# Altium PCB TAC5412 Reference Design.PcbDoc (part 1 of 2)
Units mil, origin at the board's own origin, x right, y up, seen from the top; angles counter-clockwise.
Board outline 3000 x 3000 mil, 6 copper layers (Top Layer, GND 1, Signal, GND 2, PWR, Bottom Layer), stack 60.4 mil thick; 137 components, 64 nets, 376 pads, 151 vias.
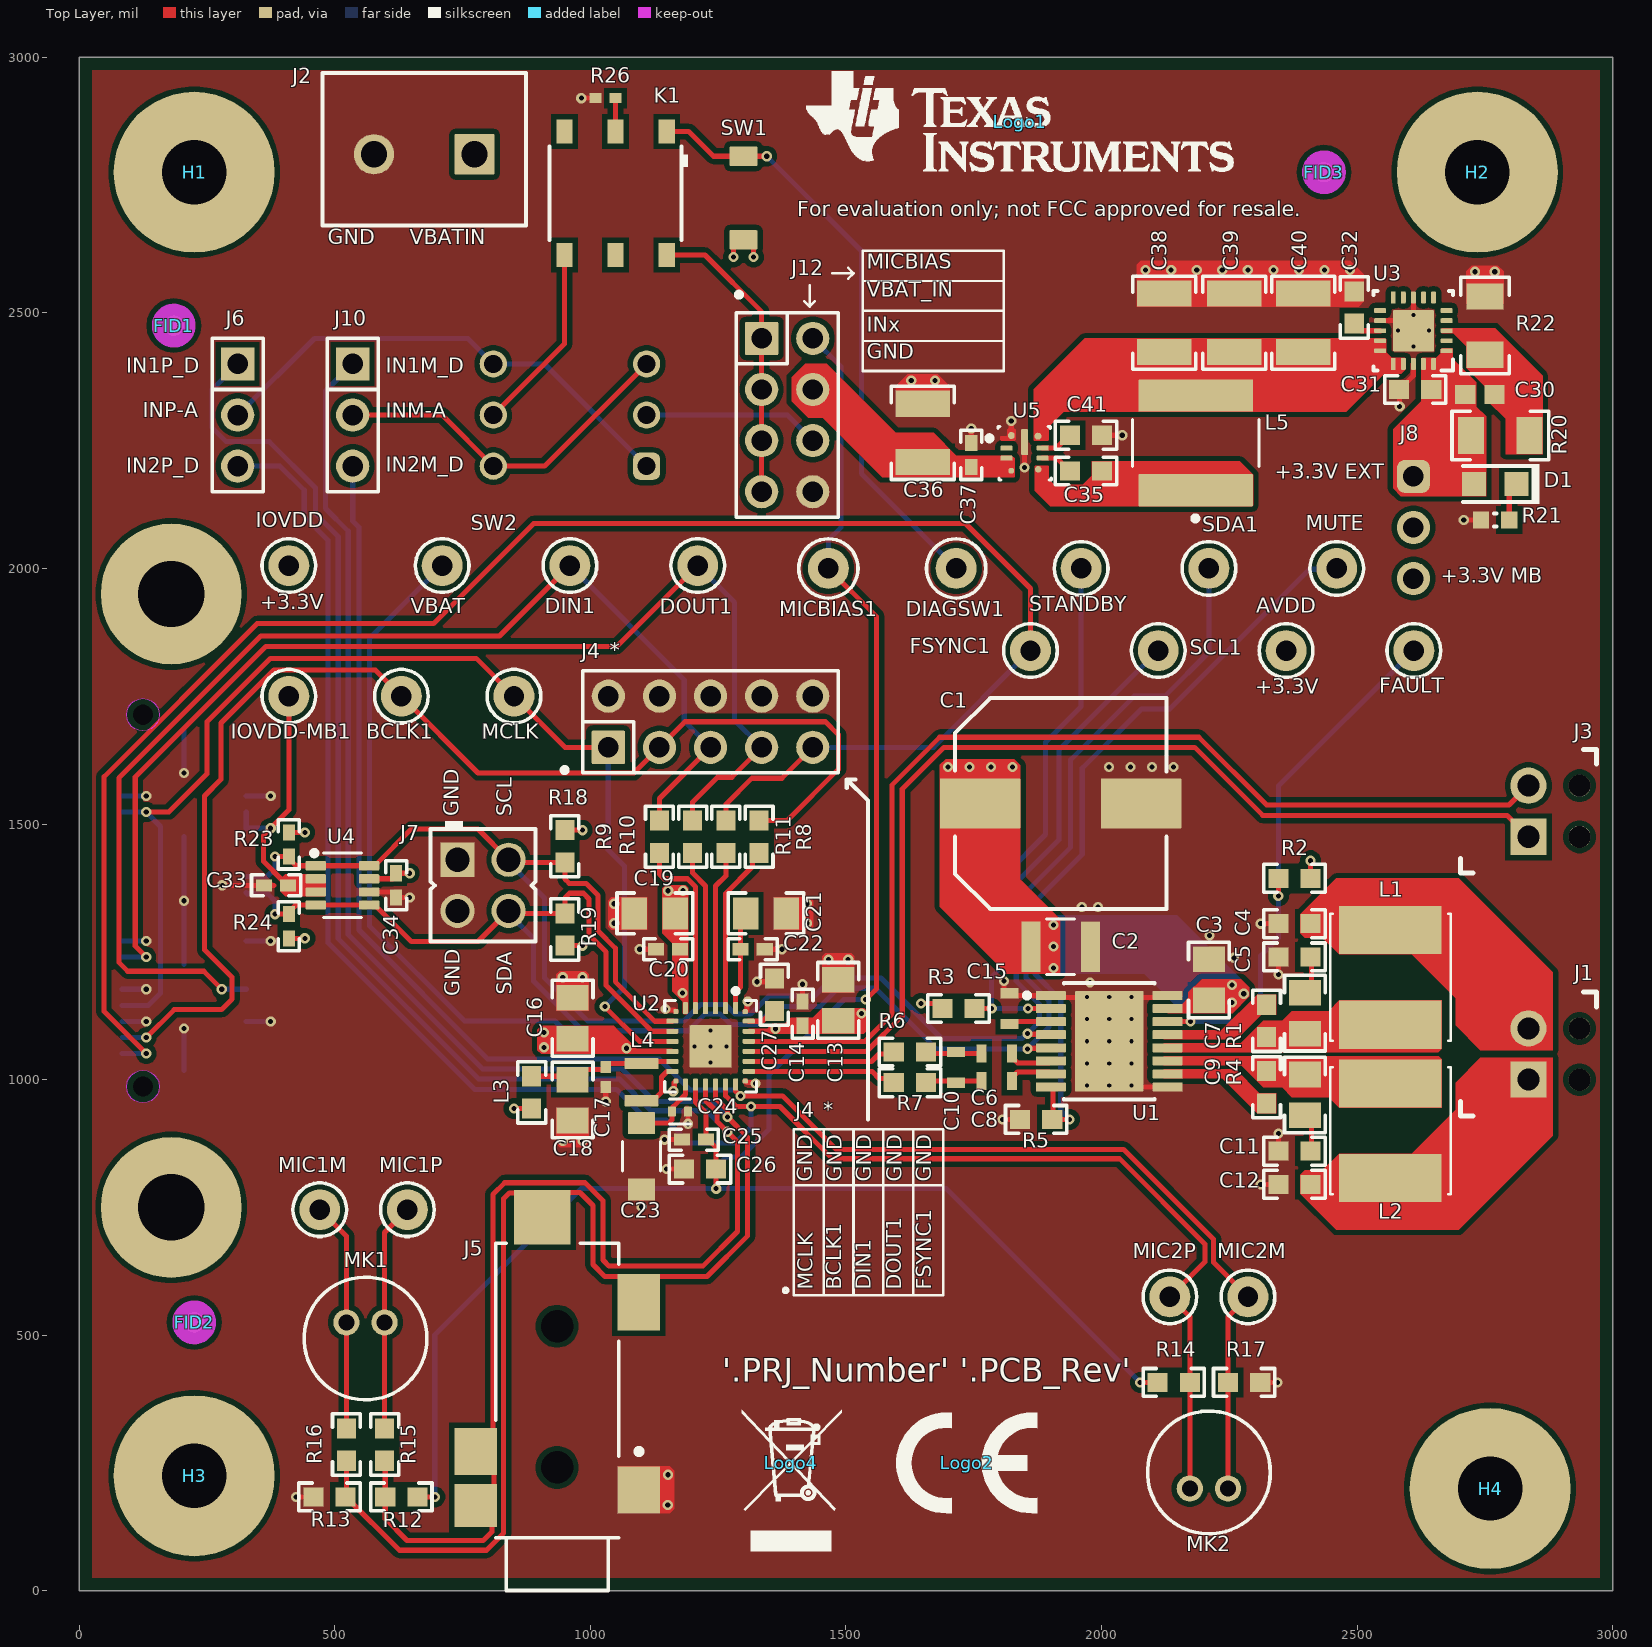
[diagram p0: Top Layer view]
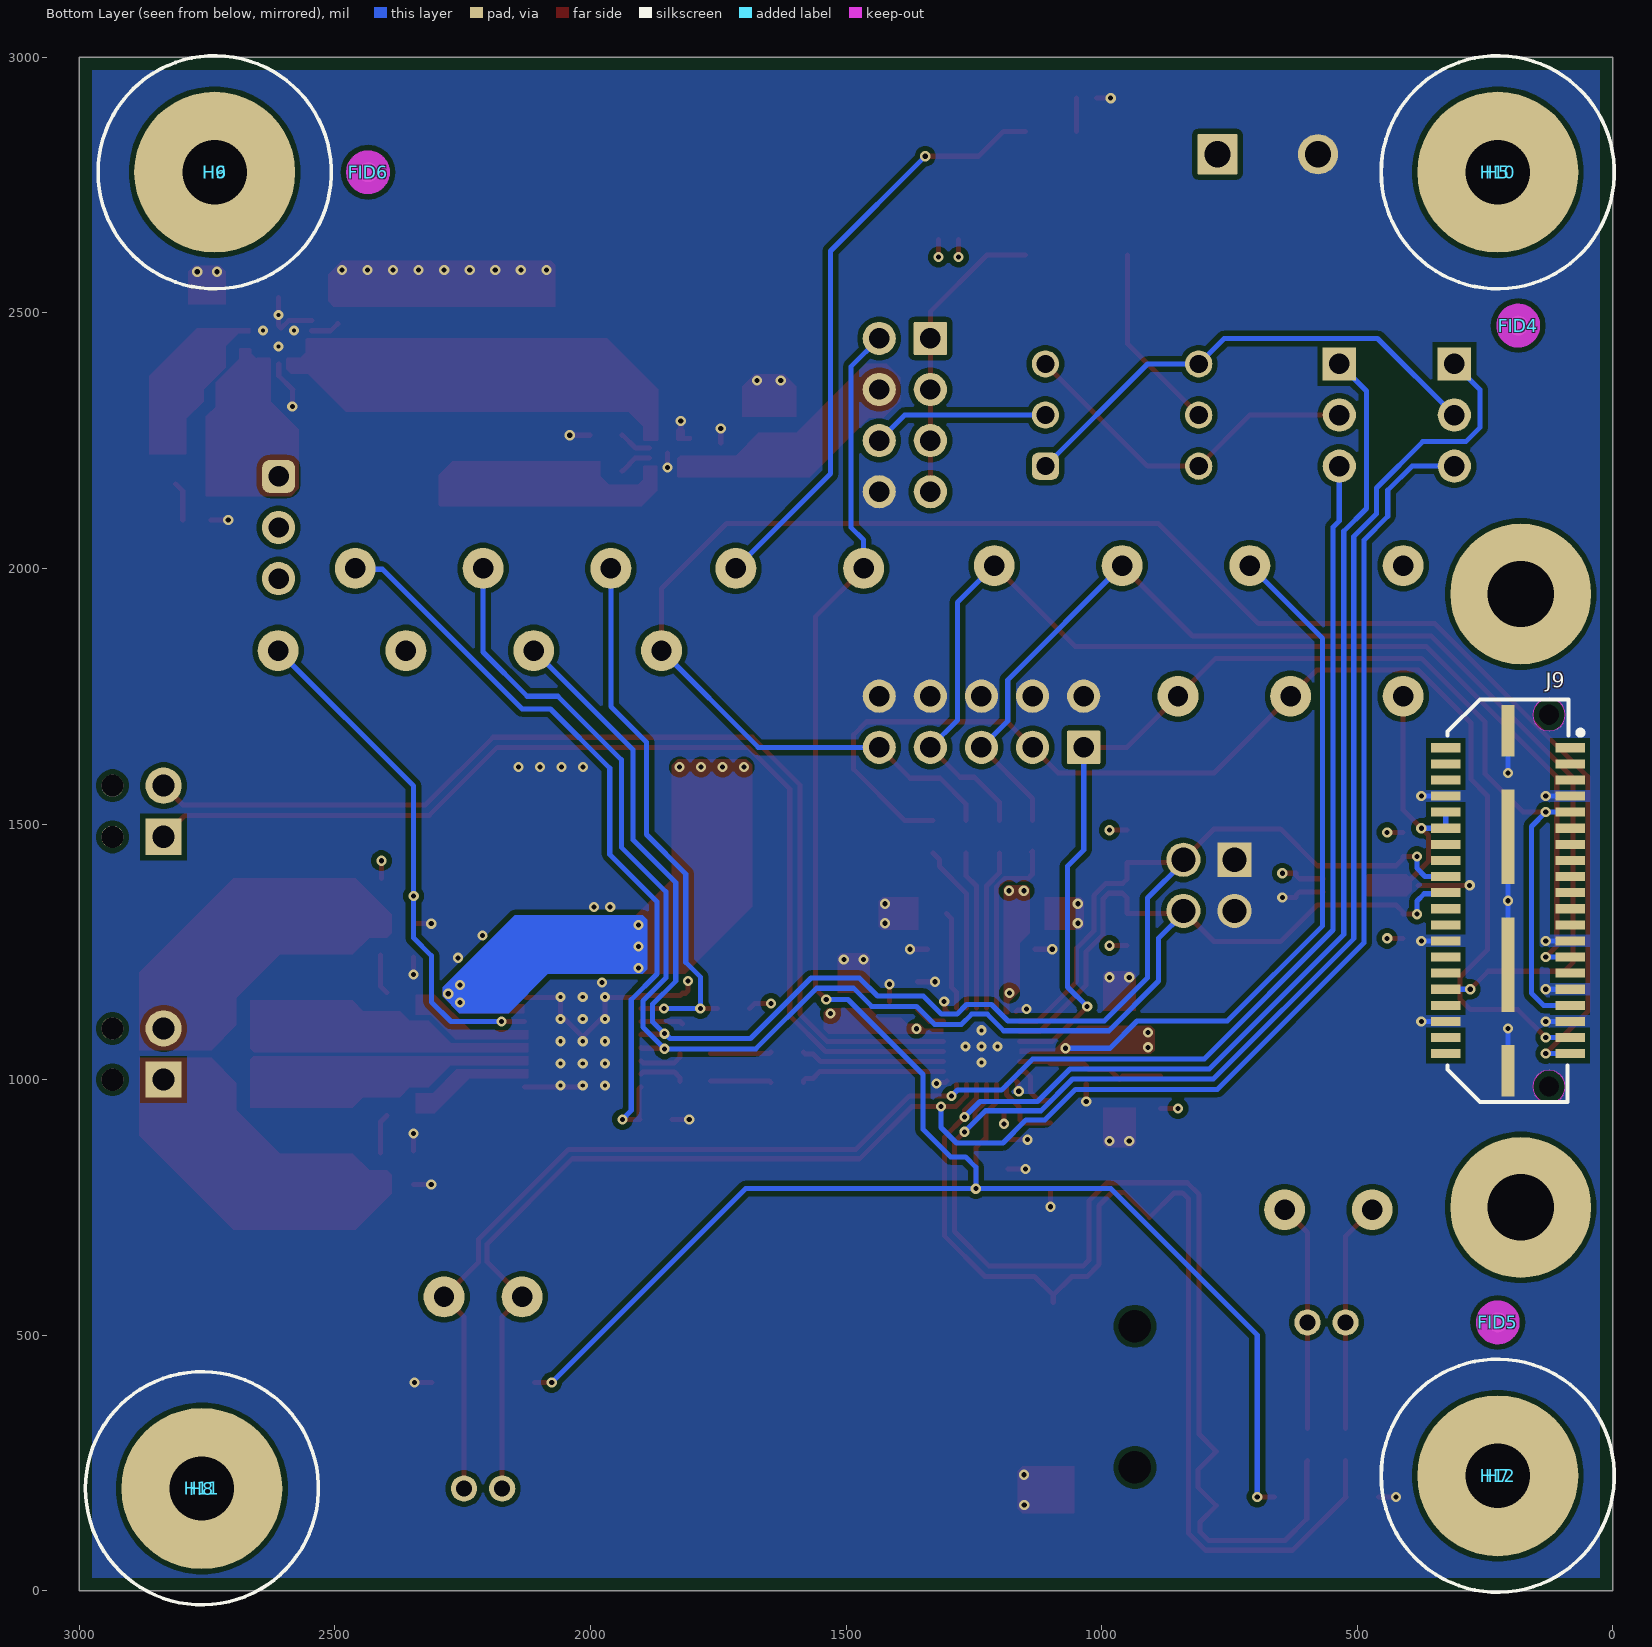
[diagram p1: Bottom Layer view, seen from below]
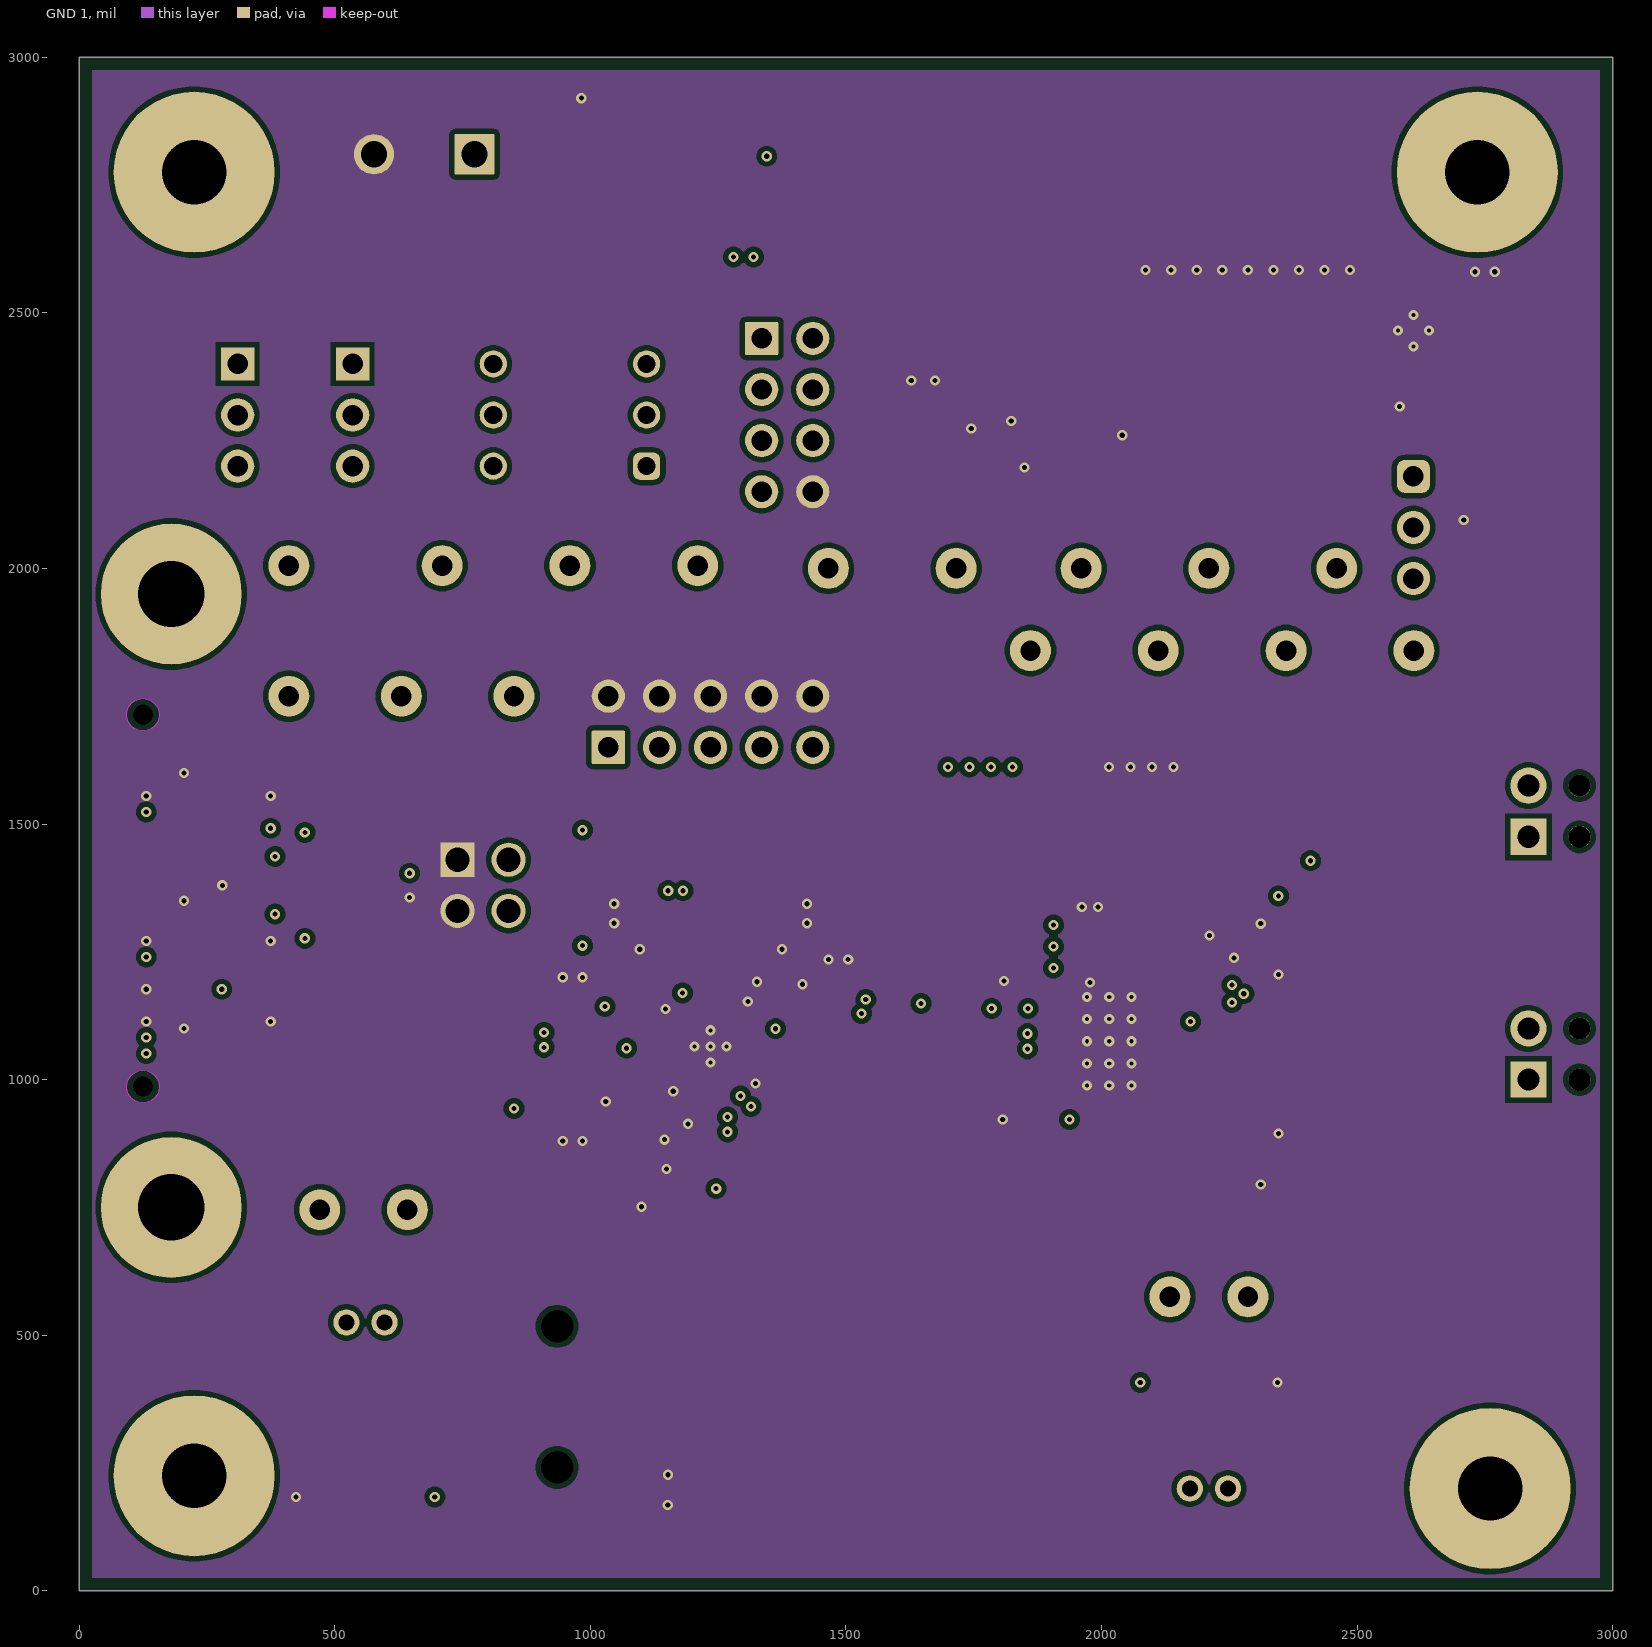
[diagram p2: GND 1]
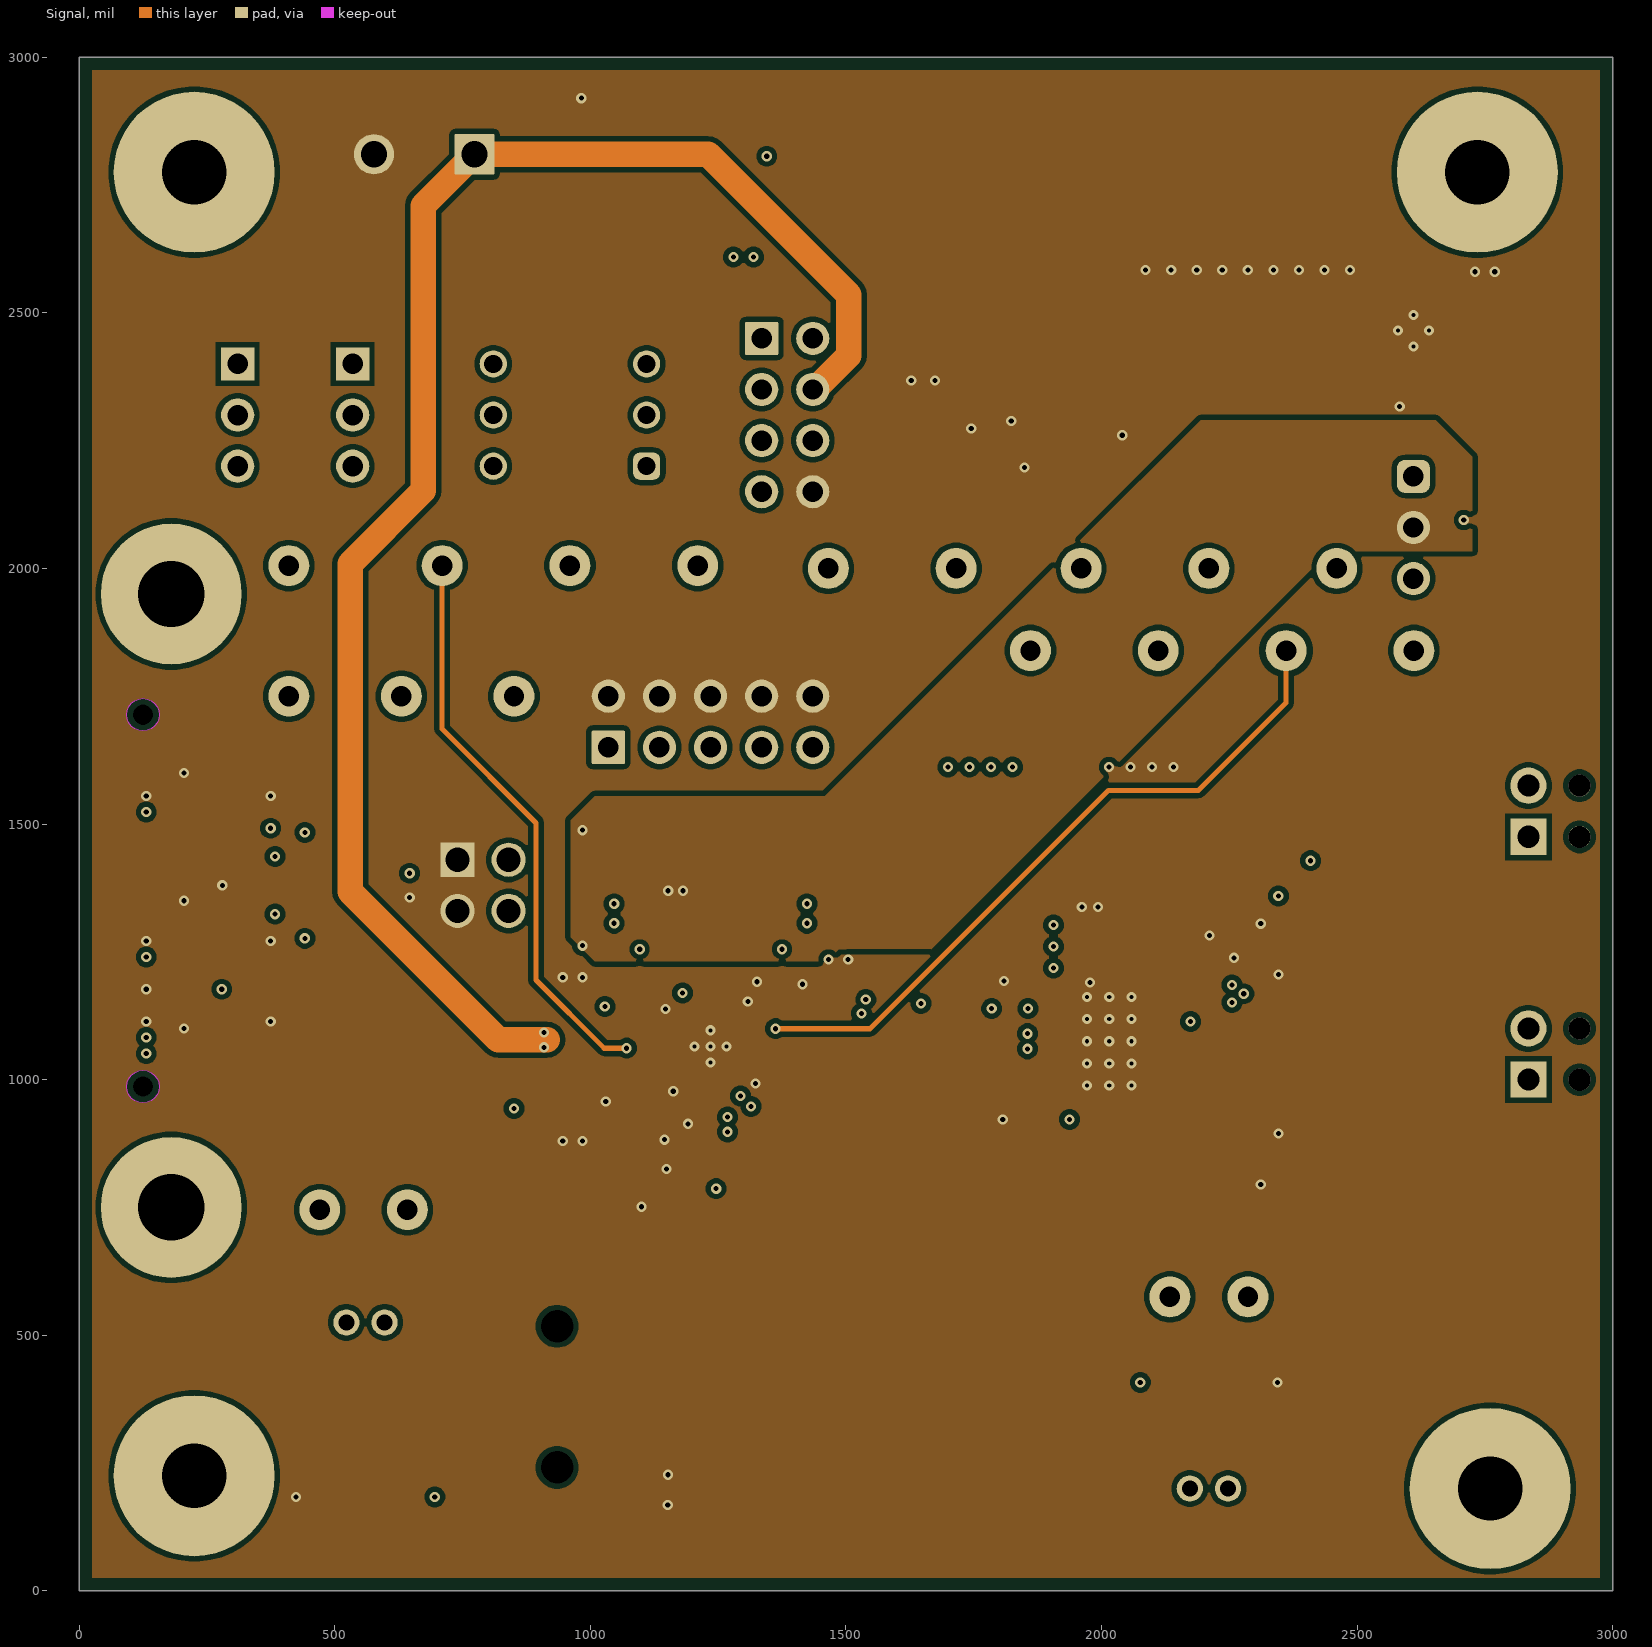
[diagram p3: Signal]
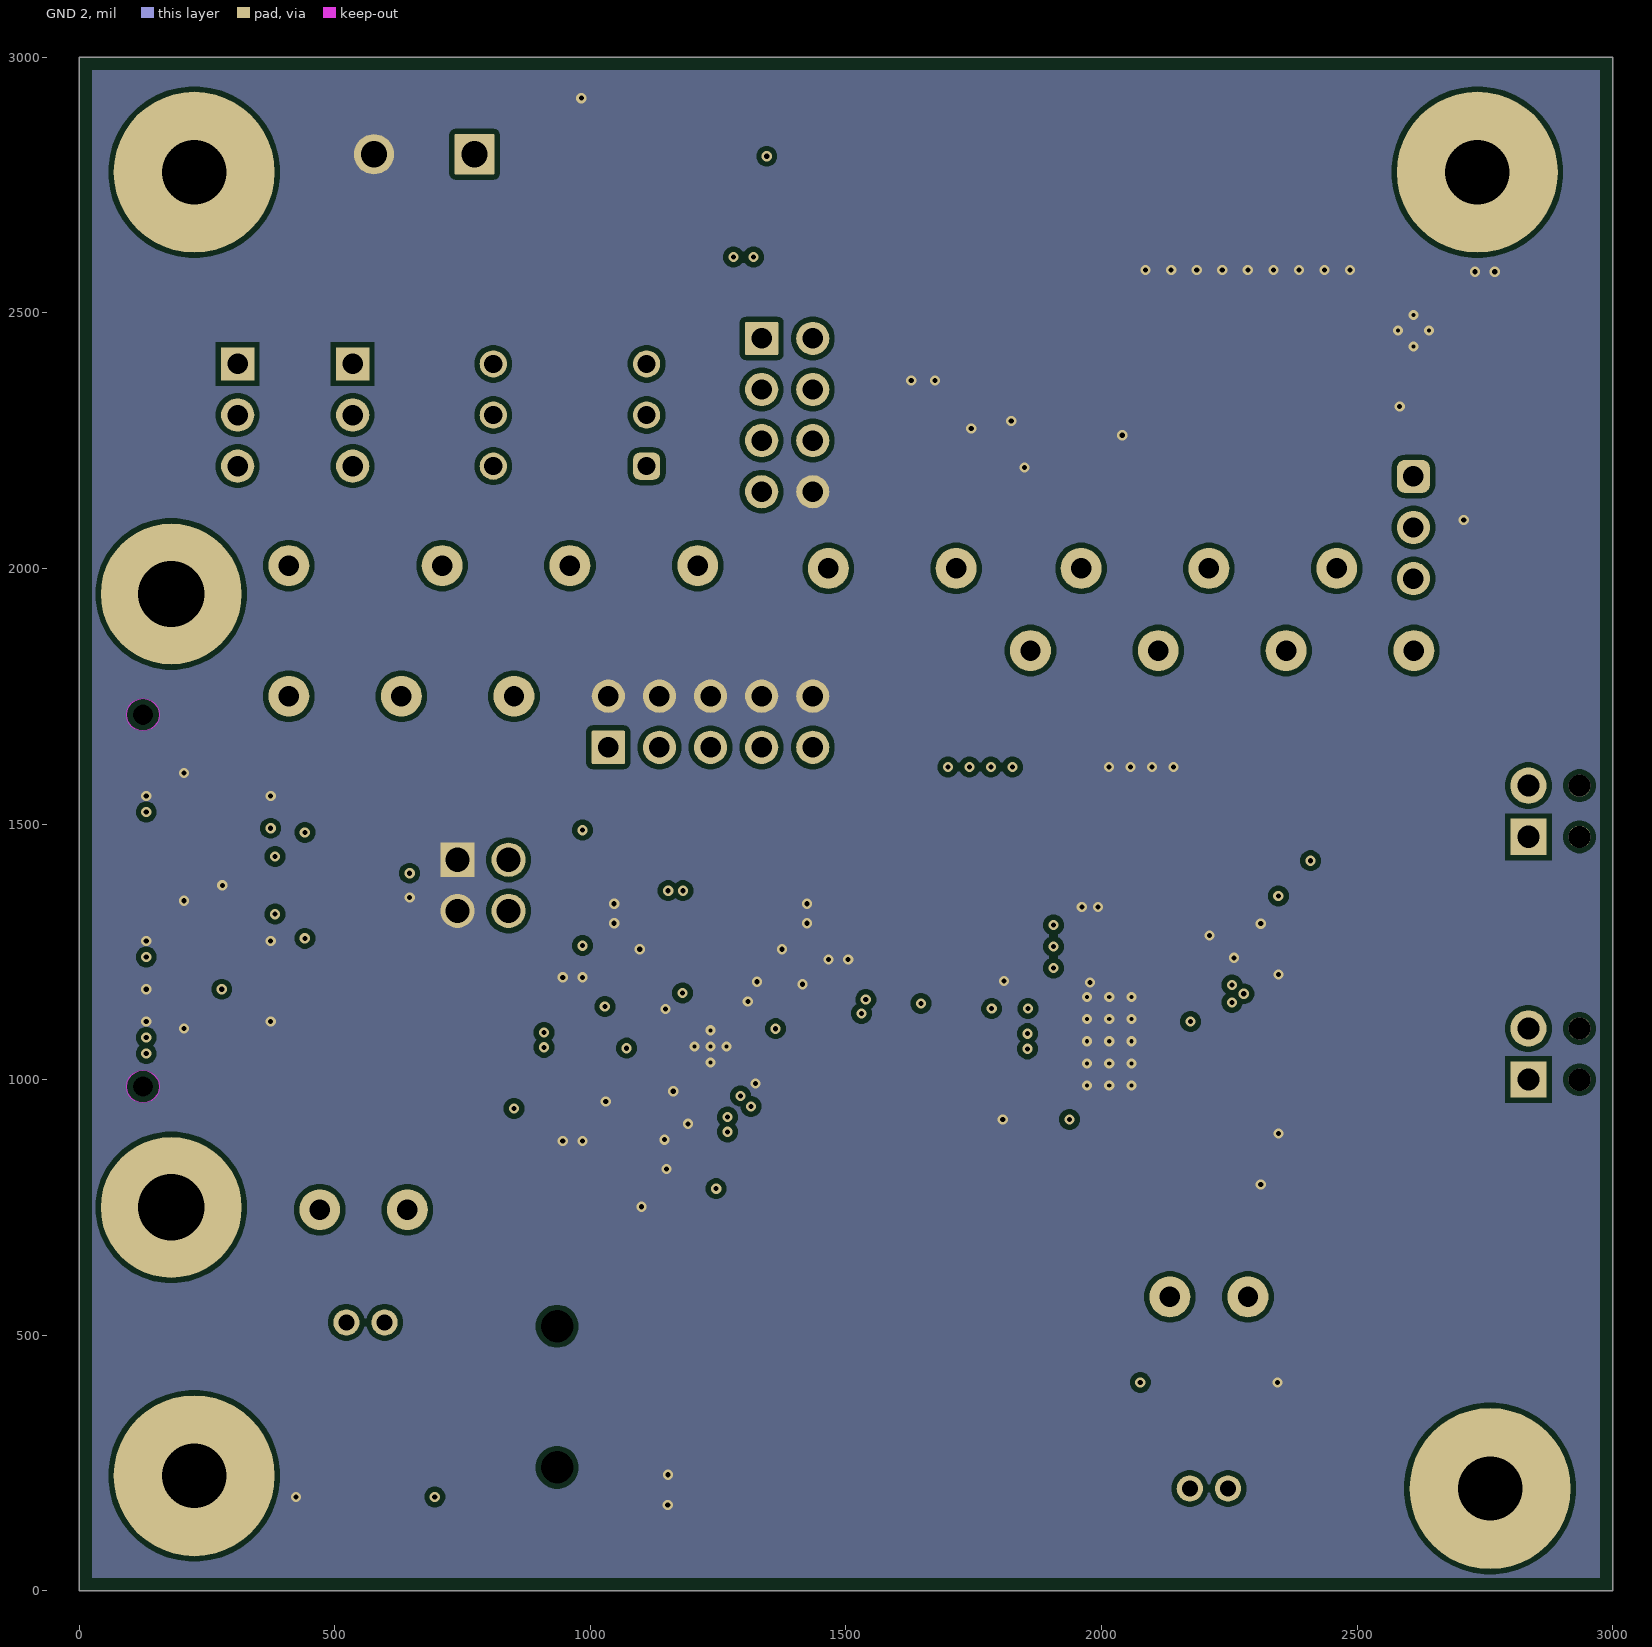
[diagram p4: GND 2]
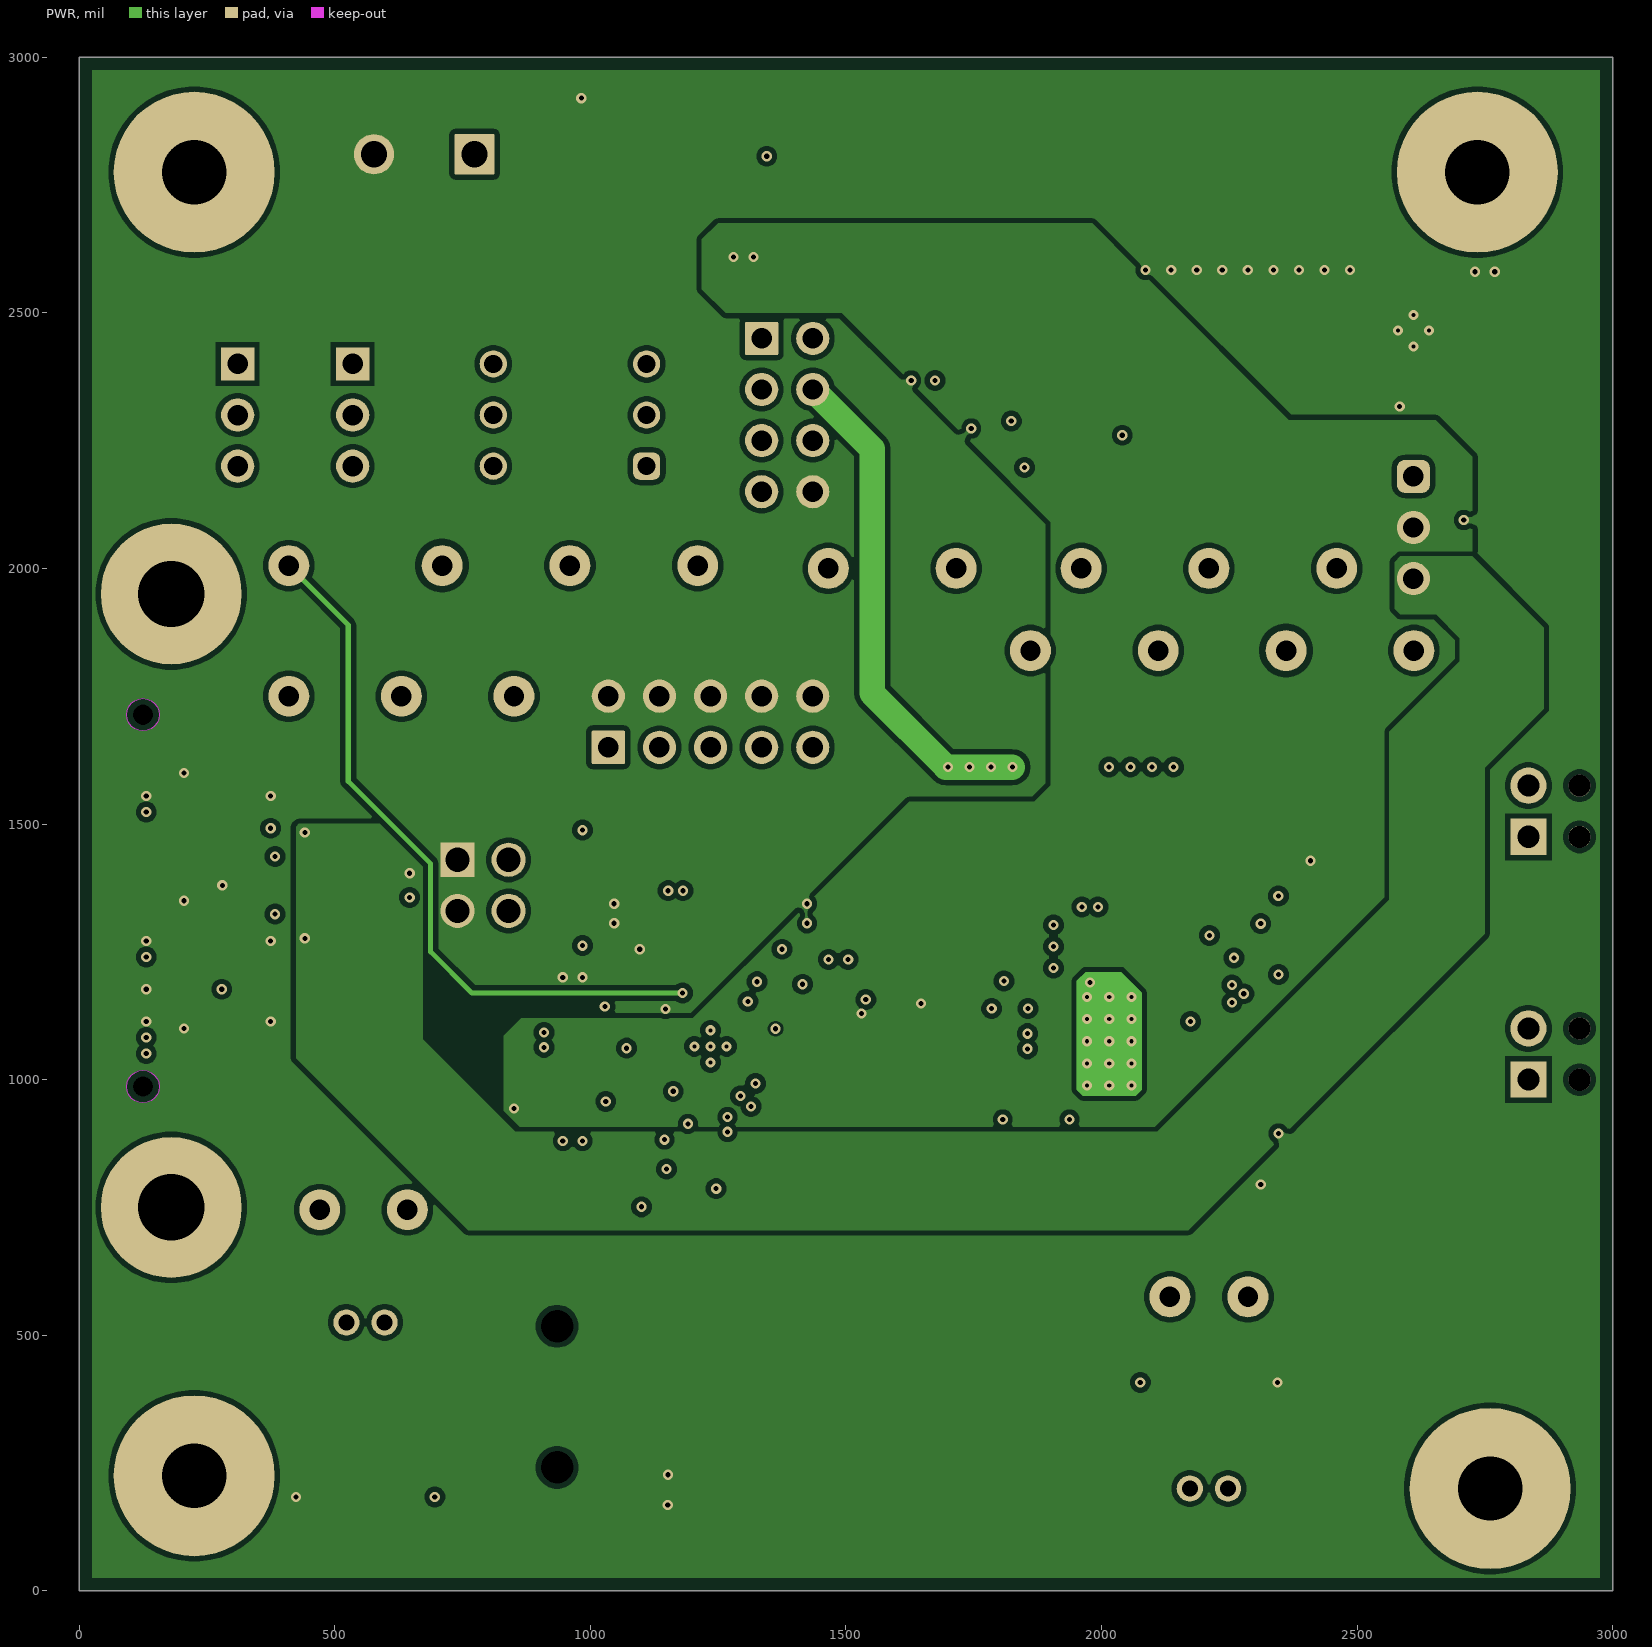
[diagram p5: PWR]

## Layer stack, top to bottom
Top Solder: solder mask 0.7, Solder Resist, Dk 3.5
Top Layer: signal copper 1.4
Dielectric 1: core 8, FR-4 High Tg, Dk 4.1
GND 1: signal copper 1.4
Dielectric 3: prepreg 8, FR-4 High Tg, Dk 4.1
Signal: signal copper 1.4
Dielectric1: core 20, FR-4 High Tg, Dk 4.1
GND 2: signal copper 1.4
Dielectric 4: prepreg 8, FR-4 High Tg, Dk 4.1
PWR: signal copper 1.4
Dielectric 2: core 8, FR-4 High Tg, Dk 4.1
Bottom Layer: signal copper 1.4
Bottom Solder: solder mask 0.7, Solder Resist, Dk 3.5

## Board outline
0,0 3000,0 3000,3000 0,3000

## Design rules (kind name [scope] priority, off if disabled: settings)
AcuteAngle [All] p1: minimum=4.50000000000000E+0001 checktracksonly=FALSE
AssemblyTestPointUsage [All] p1: valid=2
BoardOutlineClearance BoardOutlineClearance_MountingHoles [OnCopper and InComponentClass('Mounting Holes')] p1: gap=39.37 ignorepadtopadclearanceinfootprint=FALSE
BoardOutlineClearance BoardOutlineClearance_Poly [OnCopper and IsPoly] p2: gap=25 ignorepadtopadclearanceinfootprint=FALSE
BoardOutlineClearance [OnCopper and Not InComponentClass('Logo') and not InComponentClass('FiducialMark') and not InRegion(1000,500,4000,800) and not InPoly] p3: gap=40 ignorepadtopadclearanceinfootprint=FALSE
Clearance Clearance_Keepouts [((IsTrack Or IsArc) And Not InPoly) And IsFree and IsKeepOut vs ((IsTrack Or IsArc) And Not InPoly) And IsFree and IsKeepOut] p1: gap=0 ignorepadtopadclearanceinfootprint=FALSE
Clearance Clearance_Poly [InPolygon] p2: gap=10 ignorepadtopadclearanceinfootprint=TRUE
Clearance Clearance_FiducialMark [IsKeepOut and InComponentClass('FiducialMark') vs IsPad and InComponentClass('FiducialMark')] p3: gap=0 ignorepadtopadclearanceinfootprint=FALSE
Clearance [All] p4: gap=5 ignorepadtopadclearanceinfootprint=TRUE
ComponentClearance ComponentClearance_Bump [HasFootprint('Bumpon_SJ5003Transparent')] p1: gap=0 collisioncheckmode=3 verticalgap=0 showdistances=FALSE
ComponentClearance ComponentClearance_MountingHoles_FiducialMarks [InComponentClass('Mounting Holes') vs InComponentClass('FiducialMark')] p2: gap=50 collisioncheckmode=3 verticalgap=10 showdistances=FALSE
ComponentClearance ComponentClearance_Shunt [InComponentClass('Header') vs InComponentClass('Shunt')] p3: gap=0 collisioncheckmode=3 verticalgap=0 showdistances=FALSE
ComponentClearance ComponentClearance_Logo [InComponentClass('Logo')] p4: gap=30 collisioncheckmode=3 verticalgap=10 showdistances=FALSE
ComponentClearance ComponentClearance_ScrewToNut [(HasFootprint('NY PMS 440 0025 PH')) vs (HasFootprint('Keystone_1902C'))] p5: gap=5 collisioncheckmode=3 verticalgap=10 showdistances=FALSE
ComponentClearance ComponentClearance_MountingHoles [InComponentClass('Mounting Holes')] p6: gap=100 collisioncheckmode=3 verticalgap=100000 showdistances=FALSE
ComponentClearance ComponentClearance_SmallPassives [HasFootprint('0201*') or HasFootprint('0402*') or HasFootprint('0508') or HasFootprint('0603*') or HasFootprint('0612') or HasFootprint('0805*') or HasFootprint('0815*') or HasFootprint('0830*') or HasFootprint('1206*') or HasFootprint('1210*') or HasFootprint('1808*') or HasFootprint('1812*') or HasFootprint('1825*') or HasFootprint('2010*') or HasFootprint('2220*') or HasFootprint('2225*') or HasFootprint('2512*') or HasFootprint('2728*') or HasFootprint('3518*') vs HasFootprint('0201*') or HasFootprint('0402*') or HasFootprint('0508') or HasFootprint('0603*') or HasFootprint('0612') or HasFootprint('0805*') or HasFootprint('0815*') or HasFootprint('0830*') or HasFootprint('1206*') or HasFootprint('1210*') or HasFootprint('1808*') or HasFootprint('1812*') or HasFootprint('1825*') or HasFootprint('2010*') or HasFootprint('2220*') or HasFootprint('2225*') or HasFootprint('2512*') or HasFootprint('2728*') or HasFootprint('3518*')] p7: gap=14.96 collisioncheckmode=3 verticalgap=10 showdistances=FALSE
ComponentClearance ComponentClearance_THtoSMT [IsThruComponent vs IsSMTComponent] p8: gap=30 collisioncheckmode=3 verticalgap=30 showdistances=FALSE
ComponentClearance ComponentClearance_THtoTH [IsThruComponent vs IsThruComponent] p9: gap=20 collisioncheckmode=3 verticalgap=30 showdistances=FALSE
ComponentClearance [All] p10: gap=20 collisioncheckmode=3 verticalgap=10 showdistances=FALSE
DiffPairsRouting [All] p1: maxlimit=100 minlimit=10 mostfreqgap=10 toplayer_minwidth=15 toplayer_maxwidth=15 toplayer_prefwidth=15 midlayer1_minwidth=15 midlayer1_maxwidth=15 midlayer1_prefwidth=15 midlayer2_minwidth=15 midlayer2_maxwidth=15 midlayer2_prefwidth=15 midlayer3_minwidth=15 midlayer3_maxwidth=15 midlayer3_prefwidth=15 midlayer4_minwidth=15 midlayer4_maxwidth=15 midlayer4_prefwidth=15 bottomlayer_minwidth=15 bottomlayer_maxwidth=15 bottomlayer_prefwidth=15 maxuncoupledlength=1000
FabricationTestPointUsage TestPointUsage [All] p1: valid=2 allowmultiple=FALSE
FabricationTestpoint Testpoint [All] p1: side=3 testpointundercomponent=TRUE minsize=40 maxsize=100 preferedsize=60 minholesize=0 maxholesize=40 preferedholesize=32 testpointgrid=1 allowsidetop=TRUE allowsidebottom=TRUE usegrid=TRUE gridtolerance=0.01
FanoutControl Fanout_LCC [IsLCC] p1: bgadir=Out bgaviamode=Centered fanoutstyle=Auto fanoutdirection=Alternating viagrid=1 // Fanout_LCC (Default Rule)
FanoutControl Fanout_BGA [IsBGA] p2: bgadir=Out bgaviamode=Centered fanoutstyle=Auto fanoutdirection=Alternating viagrid=1 // Fanout_BGA (Default Rule)
FanoutControl Fanout_Default [All] p4: bgadir=Out bgaviamode=Centered fanoutstyle=Auto fanoutdirection=Alternating viagrid=1 // Fanout_Default (Default Rule)
FanoutControl Fanout_Small [(CompPinCount < 5)] p5: bgadir=Out bgaviamode=Centered fanoutstyle=Auto fanoutdirection=OutThenIn viagrid=1 // Fanout_Small (Default Rule)
HoleSize [All] p1: absolutevalues=TRUE maxlimit=251 minlimit=7.87 maxpercent=80.000 minpercent=20.000
MinimumAnnularRing MinimumAnnularRing_ThermalPadVias [IsVia and InAnyComponent] p1: minimumring=5.91
MinimumAnnularRing [All] p2: minimumring=5
MinimumSolderMaskSliver MinimumSolderMaskSliver_Logo [InComponentClass('Logo') vs InComponentClass('Logo')] p1: minsoldermaskwidth=0.7
MinimumSolderMaskSliver [All] p2: minsoldermaskwidth=3.94
PlaneConnect [All] p1: planeconnectstyle=Direct reliefexpansion=10 reliefentries=4 reliefconductorwidth=10 reliefairgap=10
PolygonConnect [All] p1: connectstyle=Direct reliefconductorwidth=10 reliefentries=4 polygonreliefangle="90 Angle" airgapwidth=10
RoutingVias ThermalPadVias [IsVia and InAnyComponent] p1: holewidth=7.87 width=19.68 viastyle="Through Hole" minholewidth=7.87 minwidth=19.68 maxholewidth=12.99 maxwidth=23.62
RoutingVias [All] p2: holewidth=16 width=34 viastyle="Through Hole" minholewidth=10 minwidth=20 maxholewidth=40 maxwidth=65
SilkToBoardRegionClearance [Not ((IsComment or IsDesignator) And (Hide <> 'False')) and not InRegion(1000,500,4000,800)] p1:
SilkToSilkClearance SilkToSilkClearance_Pb-FreeLogo [(HasFootprint('Pb-Free_Overlay_Medium') OR HasFootprint('Pb-Free_Overlay_Small')) vs (HasFootprint('Pb-Free_Overlay_Medium') OR HasFootprint('Pb-Free_Overlay_Small'))] p1: silktosilkclearance=0
SilkToSilkClearance [All] p2: silktosilkclearance=3.94
SilkToSolderMaskClearance SilkToComponentPadClearance [(IsPad or IsFill or IsRegion) and InAnycomponent] p1: minsilkscreentomaskgap=5 clearancetoexposedcopper=TRUE
SilkToSolderMaskClearance "Silk to Solder Mask Opening" [All] p2: minsilkscreentomaskgap=3.94 clearancetoexposedcopper=FALSE
SolderMaskExpansion [All] p1: expansion=1.97 istentingtop=FALSE
UnRoutedNet [All] p1: checkbadconnections=TRUE
Width [All] p1: maxlimit=100 minlimit=6 preferedwidth=10 checkconnectedcopper=TRUE
14 further rules are at their usual default settings.

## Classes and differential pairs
net class PWR: "+3.3V MB"
net class I2C: SCL SDA
net class ASI: BCLK1 DIN1 DIN2 DOUT1 FSYNC1
net class "16 Ohm": NetJ3_2
component class Schematic2: C30 C31 C32 C33 C34 C35 C36 C37 C38 C39 C40 C41 D1 DIAGSW1 IOVDD-MB1 J6 J8 J9 J10 J12 K1 L5 R20 R21 R22 R23 R24 R26 SW1 SW2 U3 U4 U5
component class Schematic1: AVDD BCLK1 C1 C2 C3 C4 C5 C6 C7 C8 C9 C10 C11 C12 C13 C14 C15 C16 C17 C18 C19 C20 C21 C22 C23 C24 C25 C26 C27 DIN1 DOUT1 FAULT FSYNC1 IOVDD J1 J2 J3 J4 J5 J7 L1 L2 L3 L4 MCLK MIC1M MIC1P MIC2M MIC2P MICBIAS1 MK1 MK2 MUTE R1 R2 R3 R4 R5 R6 R7 R8 R9 R10 R11 R12 R13 R14 R15 R16 R17 R18 R19 SCL1 SDA1 STANDBY U1 U2 VBAT
component class Header: J4 J6 J7 J8 J10 J12
component class "Mounting Holes": H1 H2 H3 H4
component class Logo: Logo1
component class Hardware: FID1 FID2 FID3 FID4 FID5 FID6 H1 H2 H3 H4 H5 H6 H7 H8 H9 H10 H11 H12 Logo1 Logo2 Logo3 Logo4 ZZ1 ZZ2 ZZ3 ZZ4
component class FiducialMark: FID1 FID2 FID3 FID4 FID5 FID6
component class AssemblyNote: ZZ1 ZZ2 ZZ3 ZZ4

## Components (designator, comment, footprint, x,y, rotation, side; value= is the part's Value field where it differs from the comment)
AVDD "5000" Keystone5000 2360.9,1839.35 r180 top
BCLK1 "5002" Keystone5002 630.25,1750 r180 top
C1 "UCM1H331MNL1GS" Nichicon_1000x1000 1920,1540 r0 top value=330uF
C2 "CL32B106KBJNNNE" CAP_CL32_SAM 1920,1260 r180 top
C3 "C2012X6S1H105K125AB" 0805_HV 2210,1195 r90 top value=1uF
C4 "GRM188C71E225KE11D" 0603 2377.27,1305 r180 top value=2.2uF
C5 "GRM188R72E471KW07D" 0603 2377.27,1240 r180 top value=470pF
C6 "CGA3E1X7R1E105K080AC" 0603S 1795,1051 r180 top value=1uF
C7 "GCM188R71E224KA55D" 0603 2322.75,1115 r90 top value=0.22uF
C8 "CGA3E1X7R1E105K080AC" 0603S 1795,997 r180 top value=1uF
C9 "GCM188R71E224KA55D" 0603 2322.75,985 r270 top value=0.22uF
C10 "CGA3E1X7R1E105K080AC" 0603S 1715,1024 r90 top value=1uF
C11 "GRM188R72E471KW07D" 0603 2377.27,860.02 r0 top value=470pF
C12 "GRM188C71E225KE11D" 0603 2377.27,795 r0 top value=2.2uF
C13 "EMK212BB7106KG-T" 0805_HV 1485,1155 r90 top value=10uF
C14 "885012205037" 0402 1415,1129 r90 top value=0.1uF
C15 "CGA3E1X7R1E105K080AC" 0603S 1820,1138.98 r90 top value=1uF
C16 "C2012X6S1H105K125AB" 0805_HV 965,1120 r90 top value=1uF
C17 "885012205037" 0402L 1030,1005 r270 top value=0.1uF
C18 "C2012X7R1C225K125AB" 0805_HV 965,960 r270 top value=2.2uF
C19 "EMK212BB7106KG-T" 0805_HV 1126,1325 r180 top value=10uF
C20 "885012205037" 0402 1152,1255 r180 top value=0.1uF
C21 "EMK212BB7106KG-T" 0805_HV 1343.5,1325 r0 top value=10uF
C22 "885012205037" 0402 1317.5,1255 r0 top value=0.1uF
C23 "C3216X7R1V225K160AE" FP-C3216X7R1V225K160AE_1206-MFG 1100,850 r90 top value=2.2µF
C24 "CGA2B3X7R1V104K050BB" FP-CGA2B3X7R1V104K050BB_0402-MFG 1175,937.5 r180 top value=100nF
C25 "GMK105BJ104KV-F" 0402 1202.5,882.5 r180 top value=0.1uF
C26 "C1608X7R1V105K080AC" 0603 1214.48,825 r180 top value=1uF
C27 "885012206052" 0603 1360,1166 r90 top value=1uF
C30 "C0603C103K3RACTU" CAPC17595_87N_KEM 2740,2340 r180 top
C31 "GRM188R61E106KA73D" 0603 2613.5,2350.07 r180 top value=10uF
C32 "GRM188R71E103KA01D" 0603 2494.37,2510.51 r90 top value=0.01uF
C33 "885012205037" 0402 385,1380 r0 top value=0.1uF
C34 "885012205037" 0402 620,1380 r90 top value=0.1uF
C35 "GCM188R71C105KA64J" 0603 1969.37,2190.51 r0 top value=1uF
C36 "GCM32ER71H475KA55L" 1210_270 1650,2265.09 r90 top value=4.7uF
C37 "GCM155R71H104KE02D" 0402 1745,2221.89 r90 top value=0.1uF
C38 "GRM32ER61E226KE15L" 1210_270 2122.28,2480.51 r90 top value=22uF
C39 "GRM32ER61E226KE15L" 1210_270 2259.37,2480.51 r90 top value=22uF
C40 "GRM32ER61E226KE15L" 1210_270 2394.37,2480.51 r90 top value=22uF
C41 "GCM188R71C105KA64J" 0603 1969.37,2260.51 r0 top value=1uF
D1 "LTST-C170KGKT" LTST-C170KGKT_Green 2770,2165 r0 top value=Green
DIAGSW1 "SHORT A" Keystone_5116 1715.5,2000 r90 top
DIN1 "5002" Keystone5002 960,2005.5 r0 top
DOUT1 "5002" Keystone5002 1210,2005.5 r0 top
FAULT "5002" Keystone5002 2610.9,1839.35 r180 top
FID1 "Fiducial" Fiducial10-20 185,2475 r0 top
FID2 "Fiducial" Fiducial10-20 225,525 r0 top
FID3 "Fiducial" Fiducial10-20 2435,2775 r0 top
FID4 "Fiducial" Fiducial10-20 185,2475 r180 bottom
FID5 "Fiducial" Fiducial10-20 225,525 r180 bottom
FID6 "Fiducial" Fiducial10-20 2435,2775 r180 bottom
FSYNC1 "5002" Keystone5002 1860.9,1839.35 r180 top
H1 "NY PMS 440 0025 PH" "NY PMS 440 0025 PH" 225,2775 r0 top
H2 "NY PMS 440 0025 PH" "NY PMS 440 0025 PH" 2735,2775 r0 top
H3 "NY PMS 440 0025 PH" "NY PMS 440 0025 PH" 225,225 r0 top
H4 "NY PMS 440 0025 PH" "NY PMS 440 0025 PH" 2760,200 r0 top
H5 "1902C" Keystone_1902C 225,2775 r0 bottom
H6 "1902C" Keystone_1902C 2735,2775 r0 bottom
H7 "1902C" Keystone_1902C 225,225 r0 bottom locked
H8 "1902C" Keystone_1902C 2760,200 r0 bottom
H9 "SJ-5303 (CLEAR)" Bumpon_SJ5003Transparent 2735,2775 r270 bottom
H10 "SJ-5303 (CLEAR)" Bumpon_SJ5003Transparent 225,2775 r270 bottom
H11 "SJ-5303 (CLEAR)" Bumpon_SJ5003Transparent 2760,200.5 r270 bottom
H12 "SJ-5303 (CLEAR)" Bumpon_SJ5003Transparent 225,225 r270 bottom
IOVDD "5000" Keystone5000 410,2005.5 r0 top
IOVDD-MB1 "5000" Keystone5000 410,1750 r180 top
J1 "1725656" CONN_1725656 2835,1050 r90 top
J2 "691137710002" FP-691137710002_HDR2-MFG 675,2820 r180 top
J3 "1725656" CONN_1725656 2835,1525 r90 top
J4 "TSW-105-07-G-D" TSW-105-07-G-D 1235,1700 r0 top
J5 "35RASMT4BHNTRX" Switchcraft_35RASM 935,340 r180 top
J6 "PBC03SAAN" PBC03SAAN 310,2300 r270 top
J7 "I2C" Sullins_PxC02DAAN 790,1380 r0 top
J8 "TSW-103-07-G-S" TSW-103-07-G-S 2610,2080 r270 top
J9 "QTE-020-01-L-D-A" QTE-020-01-X-D-A 205,1350 r270 bottom
J10 "PBC03SAAN" PBC03SAAN 535,2300 r270 top
J12 "TSW-104-07-G-D" TSW-104-07-G-D 1385,2300 r270 top
K1 "G3VM-31HR(TR05)" Omron_SOP-6 1049.36,2733.92 r270 top
L1 "VLS6045EX-100M-H" IND_VLS6045EX-100M-H 2565,1200 r90 top
L2 "VLS6045EX-100M-H" IND_VLS6045EX-100M-H 2565,900 r270 top
L3 "782633601" 0603 885,975 r270 top value="600 ohm"
L4 "LPWI201610H2R2T" 0806 1100,995 r270 top value=2.2uH
L5 "1255AY-3R9N=P3" "FP-1255AY-3R9N=P3_2424 (6060)-MFG" 2184.37,2245.51 r90 top value=3.9uH
Logo1 "Texas Instruments" TI_Stacked_Overlay_Small 1840.29,2874.23 r0 top
Logo2 "CE Mark" CE_Mark_5mm 1736.1,250 r0 top
Logo3 "FCC disclaimer" FCC_disclaimer 3681.67,-180 r0 top
Logo4 "WEEE logo" WEEE_Minimum 1391.96,250 r0 top
MCLK "5002" Keystone5002 850.5,1750 r180 top
MIC1M "5003" Keystone5003 470.61,745.48 r0 top
MIC1P "5003" Keystone5003 641.99,745.48 r0 top
MIC2M "5003" Keystone5003 2286.38,575 r0 top
MIC2P "5003" Keystone5003 2133.62,575 r0 top
MICBIAS1 "MBIAS" Keystone_5116 1465.5,2000 r90 top
MK1 "POM-2242P-C33-R" MIC_POM-2242P-C33-R 560,525 r180 top
MK2 "POM-2242P-C33-R" MIC_POM-2242P-C33-R 2210,200 r0 top
MUTE "5002" Keystone5002 2460,2000 r0 top
R1 "RL1220S-5R6-F" 0805_HV 2397.75,1130 r270 top value=5.60
R2 "CPF0603B100KE" 0603 2377.27,1393.68 r180 top value=100k
R3 "CPF0603B100KE" 0603 1720,1138.98 r0 top value=100k
R4 "RL1220S-5R6-F" 0805_HV 2397.75,970 r270 top value=5.60
R5 "CPF0603B100KE" 0603 1872.01,922 r0 top value=100k
R6 "RC0603JR-070RL" 0603 1625,1054 r0 top value=0
R7 "RC0603JR-070RL" 0603 1625,994 r0 top value=0
R8 "PMR03EZPJ000" 0603 1330,1475 r90 top value=0
R9 "PMR03EZPJ000" 0603 1135,1475 r90 top value=0
R10 "PMR03EZPJ000" 0603 1200,1475 r90 top value=0
R11 "PMR03EZPJ000" 0603 1265,1475 r90 top value=0
R12 "CRCW06031K10JNEA" 0603 630.18,183.55 r0 top value=1.1k
R13 "CRCW06031K10JNEA" 0603 489.59,183.62 r180 top value=1.1k
R14 "CRCW06031K10JNEA" 0603 2141.1,407.5 r0 top value=1.1k
R15 "RC0603JR-070RL" 0603 597.4,285.94 r270 top value=0
R16 "RC0603JR-070RL" 0603 522.6,285.94 r270 top value=0
R17 "CRCW06031K10JNEA" 0603 2278.9,407.5 r0 top value=1.1k
R18 "RC0603FR-071K5L" 0603 950,1456.5 r270 top value=1.50k
R19 "RC0603FR-071K5L" 0603 950,1293.5 r90 top value=1.50k
R20 "CRCW120611K8FKEA" 1206 2780,2260 r180 top value=11.8k
R21 "CRCW0603442RFKEA" 0603L 2770,2095 r180 top value=442
R22 "CRCW12063K74FKEA" 1206 2750,2475 r270 top value=3.74k
R23 "RMCF0402FT1K50" 0402 410,1460 r90 top value=1.50k
R24 "RMCF0402FT1K50" 0402 410,1300 r270 top value=1.50k
R26 "CRCW0402330RJNED" 0402L 1029.68,2919.9 r0 top value=330
SCL1 "5002" Keystone5002 2110.9,1839.35 r180 top
SDA1 "5002" Keystone5002 2210,2000 r0 top
STANDBY "5002" Keystone5002 1960,2000 r0 top
SW1 "TEST A" SW_TL1015AF160QG 1299.36,2724.58 r90 top
SW2 "76STD01T" SW_76STD01T 960,2300 r180 top
U1 "TAS5441QPWPRQ1" PWP0016B-MFG 2015,1075 r0 top
U2 "TAC5312QRGERQ1" RGE0024W-MFG 1235,1065 r270 top
U3 "TPS7A5201QRGRRQ1" RGR0020A 2610,2465 r180 top
U4 "TCA9416DDFR" SOT_16DDFR_TEX 515,1380 r0 top
U5 "LMR43620RS5QRPERQ1" RPE0009A-MFG 1849.37,2225.51 r0 top
VBAT "5000" Keystone5000 710,2005.5 r0 top
ZZ1 "This Assembly Note is for PCB labels only" AssemblyNoteLabel 41.26,3399.26 r0 top
ZZ2 "These assemblies are ESD sensitive, ESD precautions shall be observed." AssemblyNote 41.26,3290.37 r0 top
ZZ3 "These assemblies must be clean and free from flux and all contaminants. Use of no clean flux is not acceptable." AssemblyNote 41.26,3201.82 r0 top
ZZ4 "These assemblies must comply with workmanship standards IPC-A-610 Class 2, unless otherwise specified." AssemblyNote 41.26,3113.26 r0 top

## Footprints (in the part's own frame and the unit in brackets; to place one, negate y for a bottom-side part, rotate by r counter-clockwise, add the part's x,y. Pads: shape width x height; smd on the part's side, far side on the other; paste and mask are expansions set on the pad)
0402 [mm] "0402 from SM-752 data"
  rect 0.8x0.6 smd: 1(-0.6,0) 2(0.6,0)
  silkscreen extent -1.22,-0.52 1.22,0.52, body extent -0.55,-0.3 0.55,0.3, height 0.6
0402L [mm] "0402 from SM-752 data"
  rect 0.6x0.5 smd: 1(-0.5,0) 2(0.5,0)
  body extent -0.55,-0.3 0.55,0.3, height 0.6
0603 [mm] "0603 from SM-752 data"
  rect 1x0.95 smd: 1(-0.8,0) 2(0.8,0)
  silkscreen extent -1.52,-0.69 1.52,0.69, body extent -0.87,-0.47 0.87,0.47, height 1
0603L [mm] "0603 from SM-752 data"
  rect 0.8x0.85 smd: 1(-0.7,0) 2(0.7,0)
  silkscreen extent -0.07,-0.32 0.07,0.32, body extent -0.87,-0.47 0.87,0.47, height 1
0603S [mil]
  rect 20x35 smd: 1(-30,0) 2(30,0)
  body extent -34,-19 34,19, height 39
0805_HV [mil] "0805 with 30mil clearance between pads"
  rect 50x63 smd: 1(-40,0) 2(40,0)
  silkscreen extent -74,-40 74,40, body extent -43,-29 43,29, height 57
0806 [mm] "SMD, 2-Leads, Body 2x1.6mm"
  rrect18% 0.55x1.7 smd: 1(-0.925,0) 2(0.925,0)
  body extent -1.2,-0.85 1.2,0.85, height 1
1206 [mm] "1206 from SM-752 data"
  rect 1.3x1.85 smd: 1(-1.45,0) 2(1.45,0)
  silkscreen extent -2.4,-1.21 2.4,1.21, body extent -1.7,-0.9 1.7,0.9, height 1.35
1210_270 [mm] "1210"
  rect 1.3x2.7 smd: 1(-1.45,0) 2(1.45,0)
  silkscreen extent -2.32,-1.57 2.32,1.57, body extent -1.7,-1.35 1.7,1.35, height 2.7
AssemblyNote [mil] "Assembly Note"
AssemblyNoteLabel [mil] "Assembly Note for PCB Labels"
Bumpon_SJ5003Transparent [mil] "3M Hemispherical Bumpon transparent"
  round 1 on Mech4: 0(0,0)
  silkscreen extent -228,-228 228,228, body extent -219,-219 219,219, height 197
CAP_CL32_SAM [mm] "1210 from SM-752 data"
  rect 0.956x2.5 smd paste+0 mask+0: 1(-1.478,0) 2(1.478,0)
  silkscreen extent -0.69,-1.38 0.69,1.38, body extent -1.6,-1.25 1.6,1.25, height 1
CAPC17595_87N_KEM [mm]
  rect 1.006x0.95 smd paste+0 mask+0: 1(-0.728,0) 2(0.728,0)
  body extent -0.87,-0.48 0.87,0.48, height 0.87
CE_Mark_5mm [mil] "Minimum text height for CE Mark"
  silkscreen extent -138,-98 138,98
CONN_1725656 [mm] "Phoenix Contact"
  rect 1.8x1.8 hole 1.1: 1(-1.27,0)
  round 1.8 hole 1.1: 2(1.27,0)
  round 1.1 hole 1.1 unplated: MH1(-1.275,-2.54) MH2(1.27,-2.54)
  silkscreen extent -3.08,-3.37 3.08,3.37, body extent -2.77,-3.1 2.77,3.1, height 8.52
FCC_disclaimer [mil]
Fiducial10-20 [mm]
  round 1 smd mask+0.5: 1(0,0)
  Top Layer keep-out circle w1.178: c0,0 r0.5
"FP-1255AY-3R9N=P3_2424 (6060)-MFG" [mm]
  rrect6% 1.6x5.7 smd paste+0 mask+0: 1(-2.35,0) 2(2.35,0)
  silkscreen extent -3.87,-3.15 1.17,3.15, body extent -3.25,-3.25 3.25,3.25, height 0.25
FP-691137710002_HDR2-MFG [mm]
  rrect5% 2x2 hole 1.3 paste-1000 mask+0: 1(-2.5,0.25)
  round 2 hole 1.3 paste-1000 mask+0: 2(2.5,0.25)
  silkscreen extent -5.05,-3.8 5.05,3.8, body extent -5.15,-3.9 5.15,3.9, height 0.25
FP-C3216X7R1V225K160AE_1206-MFG [mm]
  rrect9% 1.1x1.35 smd paste+0 mask+0: 1(-1.65,0) 2(1.65,0)
  silkscreen extent -0.72,-0.95 0.73,0.95, body extent -2.3,-1.05 2.3,1.05, height 0.25
FP-CGA2B3X7R1V104K050BB_0402-MFG [mm]
  rrect25% 0.4x0.5 smd paste+0 mask+0: 1(-0.4,0) 2(0.4,0)
  silkscreen extent -0.52,-0.63 0.53,0.63, body extent -0.7,-0.38 0.7,0.38, height 0.25
IND_VLS6045EX-100M-H [mm]
  rect 2.4x5.1 smd: 1(-2.35,0) 2(2.35,0)
  silkscreen extent -3.15,-3 3.15,3, body extent -3.15,-3 3.15,3, height 4.5
Keystone5000 [mil] "For Keystone 500x miniature loop terminals"
  round 80 hole 40: 1(0,0)
  silkscreen extent -52,-52 52,52, body extent -49,-49 49,49, height 182
Keystone5002 [mil] "For Keystone 500x miniature loop terminals"
  round 80 hole 40: 1(0,0)
  silkscreen extent -52,-52 52,52, body extent -49,-49 49,49, height 182
Keystone5003 [mil] "For Keystone 500x miniature loop terminals"
  round 80 hole 40: 1(0,0)
  silkscreen extent -52,-52 52,52, body extent -49,-49 49,49, height 182
Keystone_1902C [mil] "Hex Standoff, 4-40 threaded, nylon"
  round 1 on Mech4: 0(0,0)
  body extent -145,-126 146,126, height 501
Keystone_5116 [mil] "For Keystone 500x miniature loop terminals"
  round 80 hole 40: 1(0,0)
  silkscreen extent -58,-58 58,58, body extent -50,-49 50,51, height 183
LTST-C170KGKT_Green [mm] "LITE-ON"
  rect 1.2x1.2 smd: 1(-1.05,0) 2(1.05,0)
  silkscreen extent -1.6,-1 2.2,1, body extent -1.05,-0.67 1.05,0.67, height 1.1
MIC_POM-2242P-C33-R [mm] "POM Audio"
  round 1.3 hole 0.8: 1(-0.95,0) 2(0.95,0)
  silkscreen extent -3.05,-2.25 3.05,3.85, body extent -3.05,-2.24 3.05,3.84, height 2.5
Nichicon_1000x1000 [mm] "SMD, 2-Leads, Dia 10mm"
  rrect4% 4x2.5 smd: 1(-4,0) 2(4,0)
  silkscreen extent -5.25,-5.25 5.25,5.25, body extent -5.25,-5.25 5.25,5.25, height 10.81
"NY PMS 440 0025 PH" [mm] "4-40 nylon screw and mounting hole"
  round 8 hole 3.2: 1(0,0)
  body extent -3.3,-3.3 3.3,3.3, height 2.69
Omron_SOP-6 [mm] "SOP, 6-Leads, Body 6.3x4.4mm, Pitch 2.54mm"
  rect 1.2x0.8 smd: 1(-3.075,2.54) 2(-3.075,0) 3(-3.075,-2.54) 4(3.075,-2.54) 5(3.075,0) 6(3.075,2.54)
  silkscreen extent -2.32,-3.28 2.32,3.6, body extent -2.32,-3.28 2.32,3.27, height 2.11
PBC03SAAN [mm] "Sullins 100mil, 1x3, 230 mil above insulator"
  rect 1.65x1.65 hole 1.016: 1(-2.54,0)
  round 1.65 hole 1.016: 2(0,0) 3(2.54,0)
  silkscreen extent -3.81,-1.27 3.81,1.27, body extent -3.81,-1.27 3.81,1.27, height 8.38
PWP0016B-MFG [mm]
  rrect22% 1.5x0.45 smd paste+0 mask+0: 1(-2.9,2.275) 2(-2.9,1.625) 3(-2.9,0.975) 4(-2.9,0.325) 5(-2.9,-0.325) 6(-2.9,-0.975) 7(-2.9,-1.625) 8(-2.9,-2.275) 9(2.9,-2.275) 10(2.9,-1.625) 11(2.9,-0.975) 12(2.9,-0.325) 13(2.9,0.325) 14(2.9,0.975) 15(2.9,1.625) 16(2.9,2.275)
  rrect3% 3.4x5 smd paste-1000 mask-1000: 17(0,0)
  silkscreen extent -4.22,-2.9 2.25,2.9, body extent -3.75,-2.8 3.75,2.8, height 0.25
QTE-020-01-X-D-A [mm] "0.80mm pitch, 40 pin, high speed terminal strip"
  rect 0.45x1.45 smd: 1(-7.6,3.09) 2(-7.6,-3.09) 3(-6.8,3.09) 4(-6.8,-3.09) 5(-6,3.09) 6(-6,-3.09) 7(-5.2,3.09) 8(-5.2,-3.09) 9(-4.4,3.09) 10(-4.4,-3.09) 11(-3.6,3.09) 12(-3.6,-3.09) 13(-2.8,3.09) 14(-2.8,-3.09) 15(-2,3.09) 16(-2,-3.09) 17(-1.2,3.09) 18(-1.2,-3.09) 19(-0.4,3.09) 20(-0.4,-3.09) 21(0.4,3.09) 22(0.4,-3.09) 23(1.2,3.09) 24(1.2,-3.09) 25(2,3.09) 26(2,-3.09) 27(2.8,3.09) 28(2.8,-3.09) 29(3.6,3.09) 30(3.6,-3.09) 31(4.4,3.09) 32(4.4,-3.09) 33(5.2,3.09) 34(5.2,-3.09) 35(6,3.09) 36(6,-3.09) 37(6.8,3.09) 38(6.8,-3.09) 39(7.6,3.09) 40(7.6,-3.09)
  rect 2.55x0.65 smd: 41(-8.445,0) 44(8.445,0)
  rect 4.7x0.65 smd: 42(-3.175,0) 43(3.175,0)
  round 0.5 hole 1 unplated: 45(-9.24,2.04) 46(9.24,2.04)
  Keep-Out Layer pour cut-out: 10.047,2.04 10.019,2.249 9.939,2.443 9.811,2.611 9.643,2.739 9.449,2.819 9.24,2.847 9.031,2.819 8.837,2.739 8.669,2.611 8.541,2.443 8.461,2.249 8.433,2.04 8.461,1.831 8.541,1.637 8.669,1.469 8.837,1.341 9.031,1.261 9.24,1.233 9.449,1.261 9.643,1.341 9.811,1.469 9.939,1.637 10.019,1.831
  Keep-Out Layer pour cut-out: -8.433,2.04 -8.461,2.249 -8.541,2.443 -8.669,2.611 -8.837,2.739 -9.031,2.819 -9.24,2.847 -9.449,2.819 -9.643,2.739 -9.811,2.611 -9.939,2.443 -10.019,2.249 -10.047,2.04 -10.019,1.831 -9.939,1.637 -9.811,1.469 -9.643,1.341 -9.449,1.261 -9.24,1.233 -9.031,1.261 -8.837,1.341 -8.669,1.469 -8.541,1.637 -8.461,1.831
  silkscreen extent -10,-3 10,3.72, body extent -10.01,-3.56 9.99,3.56, height 4.27
RGE0024W-MFG [mm]
  rrect40% 0.6x0.25 smd paste+0 mask+0: 1(-1.9,1.25) 2(-1.9,0.75) 3(-1.9,0.25) 4(-1.9,-0.25) 5(-1.9,-0.75) 6(-1.9,-1.25) 13(1.9,-1.25) 14(1.9,-0.75) 15(1.9,-0.25) 16(1.9,0.25) 17(1.9,0.75) 18(1.9,1.25)
  rrect40% 0.25x0.6 smd paste+0 mask+0: 7(-1.25,-1.9) 8(-0.75,-1.9) 9(-0.25,-1.9) 10(0.25,-1.9) 11(0.75,-1.9) 12(1.25,-1.9) 19(1.25,1.9) 20(0.75,1.9) 21(0.25,1.9) 22(-0.25,1.9) 23(-0.75,1.9) 24(-1.25,1.9)
  rrect5% 2.1x2.1 smd paste-1000 mask+0: 25(0,0)
  rrect40% 0.25x0.25 smd paste+0 mask+0: A1(-1.725,1.725) A2(-1.725,-1.725) A3(1.725,-1.725) A4(1.725,1.725)
  silkscreen extent -2.87,-2.27 2.27,2.27, body extent -2.3,-2.3 2.3,2.3, height 0.25
RGR0020A [mm] "QFN, 20-Leads, Body 3.5x3.5mm, Pitch 0.5mm, Thermal Pad 2.05x2.05mm, TI Recommended"
  rrect42% 0.6x0.24 smd: 1(-1.65,1) 2(-1.65,0.5) 3(-1.65,0) 4(-1.65,-0.5) 5(-1.65,-1) 11(1.65,-1) 12(1.65,-0.5) 13(1.65,0) 14(1.65,0.5) 15(1.65,1)
  rrect42% 0.24x0.6 smd: 6(-1,-1.65) 7(-0.5,-1.65) 8(0,-1.65) 9(0.5,-1.65) 10(1,-1.65) 16(1,1.65) 17(0.5,1.65) 18(0,1.65) 19(-0.5,1.65) 20(-1,1.65)
  rrect5% 2.05x2.05 smd paste-1.025: 21(0,0)
  silkscreen extent -1.97,-1.97 1.97,1.97, body extent -1.75,-1.75 1.75,1.75, height 1
RPE0009A-MFG [mm]
  round 0.342 smd paste-1000 mask+0: 1(-0.661,0.877)
  rrect40% 0.6x0.25 smd paste+0 mask+0: 2(-0.9,0.25) 3(-0.9,-0.25) 6(0.9,-0.25) 7(0.9,0.25)
  round 0.291 smd paste+0 mask+0: 4(-0.661,-0.877)
  round 0.323 smd paste+0 mask+0: 5(0.68,-0.805)
  round 0.346 smd paste-1000 mask+0: 8(0.665,0.841)
  rrect29% 0.35x1.3 smd paste-1000 mask+0: 9(0,0.55)
  Top Layer region: 1.2,0.8 1.193,0.825 1.175,0.844 1.15,0.85 1.15,0.85 0.9,0.851 0.881,0.854 0.865,0.865 0.854,0.881 0.85,0.901 0.85,0.901 0.85,1.15 0.843,1.175 0.825,1.193 0.8,1.2 0.8,1.2 0.5,1.2 0.481,1.196 0.465,1.185 0.454,1.169 0.45,1.15 0.45,1.15 0.45,0.676 0.454,0.656 0.465,0.64 0.481,0.629 0.5,0.625 0.5,0.625 1.15,0.626 1.169,0.629 1.185,0.64 1.196,0.656 1.2,0.675 1.2,0.676
  Top Layer region: -1.2,0.8 -1.193,0.826 -1.175,0.844 -1.15,0.851 -1.15,0.851 -0.9,0.851 -0.881,0.854 -0.865,0.865 -0.854,0.881 -0.85,0.901 -0.85,0.901 -0.85,1.15 -0.843,1.175 -0.825,1.193 -0.8,1.2 -0.8,1.2 -0.5,1.2 -0.481,1.196 -0.465,1.185 -0.454,1.169 -0.45,1.15 -0.45,1.15 -0.45,0.676 -0.454,0.656 -0.465,0.64 -0.481,0.629 -0.5,0.626 -0.5,0.625 -1.15,0.626 -1.169,0.629 -1.185,0.64 -1.196,0.656 -1.2,0.676 -1.2,0.676
  Top Layer region: 1.2,-0.8 1.193,-0.825 1.175,-0.844 1.15,-0.85 1.15,-0.851 0.9,-0.85 0.881,-0.854 0.865,-0.865 0.854,-0.881 0.85,-0.9 0.85,-0.901 0.85,-1.15 0.843,-1.175 0.825,-1.193 0.8,-1.2 0.8,-1.2 0.55,-1.2 0.531,-1.196 0.515,-1.185 0.504,-1.169 0.5,-1.15 0.5,-1.15 0.5,-0.676 0.504,-0.656 0.515,-0.64 0.531,-0.629 0.55,-0.625 0.55,-0.625 1.15,-0.626 1.169,-0.629 1.185,-0.64 1.196,-0.656 1.2,-0.676 1.2,-0.676
  Top Layer region: -1.2,-0.8 -1.193,-0.825 -1.175,-0.844 -1.15,-0.85 -1.15,-0.85 -0.9,-0.851 -0.881,-0.854 -0.865,-0.865 -0.854,-0.881 -0.85,-0.901 -0.85,-0.901 -0.85,-1.15 -0.843,-1.175 -0.825,-1.193 -0.8,-1.2 -0.8,-1.2 -0.55,-1.2 -0.531,-1.196 -0.515,-1.185 -0.504,-1.169 -0.5,-1.15 -0.5,-1.15 -0.5,-0.676 -0.504,-0.656 -0.515,-0.64 -0.531,-0.629 -0.55,-0.625 -0.55,-0.625 -1.15,-0.626 -1.169,-0.629 -1.185,-0.64 -1.196,-0.656 -1.2,-0.676 -1.2,-0.676
  silkscreen extent -1.87,-1.33 1.33,1.33, body extent -1.3,-1.3 1.3,1.3, height 0.25
SOT_16DDFR_TEX [mil]
  rrect20% 39.5x18 smd paste+0 mask+0: 1(-52.25,38.39) 2(-52.25,12.8) 3(-52.25,-12.8) 4(-52.25,-38.39) 5(52.25,-38.39) 6(52.25,-12.8) 7(52.25,12.8) 8(52.25,38.39)
  silkscreen extent -60,-63 38,68, body extent -58,-58 58,58, height 43
Sullins_PxC02DAAN [mm] "Header, 2.54mm, 2x2, TH"
  rect 1.7x1.7 hole 1.2: 1(-1.27,1.27)
  round 1.7 hole 1.2: 2(1.27,1.27) 3(-1.27,-1.27) 4(1.27,-1.27)
  silkscreen extent -2.61,-2.8 2.61,3.2, body extent -2.61,-2.8 2.61,2.8, height 8.58
SW_76STD01T [mm] "TH, 6-Leads, Body 9.65x9.65mm"
  rrect50% 1.35x1.35 hole 0.9: 1(-3.81,2.54)
  round 1.35 hole 0.9: 2(-3.81,0) 3(-3.81,-2.54) 4(3.81,-2.54) 5(3.81,0) 6(3.81,2.54)
  body extent -4.83,-4.83 4.82,4.83, height 11.86
SW_TL1015AF160QG [mm] "E-Switch"
  rrect11% 0.95x1.4 smd: 1(-2.075,0) 2(2.075,0)
  body extent -2.3,-1.5 2.3,1.5, height 2
Switchcraft_35RASM [mil] "Switchcraft"
  rect 83x92 smd: 1(-159.5,142.5) 2(159.5,67.5)
  rect 83x111 smd: 3(-159.5,-224.5)
  rect 83x84 smd: 4(159.5,173.5)
  rect 111x107 smd: 5(29,-390.5)
  rect 0x0 hole 63 unplated: MH1(0,98.5) MH2(0,-177.5)
  silkscreen extent -161,-340 121,340, body extent -120,-339 120,340, height 202
TI_Stacked_Overlay_Small [mil]
  silkscreen extent -418,-98 418,98
TSW-103-07-G-S [mm] "Samtec 100mil, 1x3, 230 mil above insulator"
  rrect50% 1.65x1.65 hole 1.016: 1(-2.54,0)
  round 1.65 hole 1.016: 2(0,0) 3(2.54,0)
  body extent -3.81,-1.27 3.81,1.27, height 8.38
TSW-104-07-G-D [mm] "Samtec 100mil, 2x4, 230 mil above insulator"
  rrect6% 1.65x1.65 hole 1.016: 1(-3.81,-1.27)
  round 1.65 hole 1.016: 2(-3.81,1.27) 3(-1.27,-1.27) 4(-1.27,1.27) 5(1.27,-1.27) 6(1.27,1.27) 7(3.81,-1.27) 8(3.81,1.27)
  silkscreen extent -6.1,-2.54 5.08,2.54, body extent -5.08,-2.54 5.08,2.54, height 8.38
TSW-105-07-G-D [mm] "Samtec 100mil, 2x5, 230 mil above insulator"
  rrect6% 1.65x1.65 hole 1.016: 1(-5.08,-1.27)
  round 1.65 hole 1.016: 2(-5.08,1.27) 3(-2.54,-1.27) 4(-2.54,1.27) 5(0,-1.27) 6(0,1.27) 7(2.54,-1.27) 8(2.54,1.27) 9(5.08,-1.27) 10(5.08,1.27)
  silkscreen extent -7.37,-2.54 6.35,2.54, body extent -6.35,-2.54 6.35,2.54, height 8.38
WEEE_Minimum [mil] "WEEElie bin"
  silkscreen extent -95,-172 99,104

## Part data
AVDD IOVDD IOVDD-MB1 VBAT: library part CMP-0055137-2, "Test Point, Miniature, Red, TH", Color=Red, Manufacturer="Keystone Electronics", Supplier Part Number 1=36-5000-ND
BCLK1 DIN1 DOUT1 FAULT FSYNC1 MCLK MUTE SCL1 SDA1 STANDBY: library part CMP-0055139-2, "Test Point, Miniature, White, TH", Color=White, Manufacturer="Keystone Electronics", Supplier Part Number 1=36-5002-ND
C1: library part CMP-0064900-1, "CAP, AL, 330 uF, 50 V, +/- 20%, SMD", Cap_Case=10x10mm, Manufacturer=Nichicon, Supplier Part Number 1=493-14535-1-ND, Tolerance_%=20%, Value1=Unknown, Value2=50V, ValueDisplayed=330uF
C2: "No Description Available", Mfr_Name=Samsung
C3 C16: library part CMP-0007855-1, "CAP, CERM, 1 uF, 50 V, +/- 10%, X6S, 0805", Cap_Case=0805, Manufacturer=TDK, Supplier Part Number 1=445-7595-1-ND, TempCo=X6S, Tolerance_%=10%, Value1="0.008782 ohm", Value2=50V, ValueDisplayed=1uF
C4 C12: library part CMP-0075366-3, "CAP, CERM, 2.2 µF, 25 V,+/- 10%, X7S, 0603", Cap_Case=0603, Manufacturer=MuRata, Supplier Part Number 1=490-12732-1-ND, TempCo=X7S, Tolerance_%=10%, Value2=25V, ValueDisplayed=2.2µF
C5 C11: library part CMP-0007495-4, "CAP, CERM, 470 pF, 250 V, +/- 10%, X7R, 0603", Cap_Case=0603, Manufacturer=MuRata, Supplier Part Number 1=490-3523-1-ND, TempCo=X7R, Tolerance_%=10%, Value1=Unknown, Value2=250V, ValueDisplayed=470pF
C6 C8 C10 C15: library part CMP-0076705-3, "CAP, CERM, 1 µF, 25 V,+/- 10%, X7R, AEC-Q200 Grade 1, 0603", Cap_Case=1.6x0.8x0.8mm, Manufacturer=TDK, Supplier Part Number 1=445-6931-1-ND, TempCo=X7R, Tolerance_%=10%, Value2=25V, ValueDisplayed=1µF
C7 C9: library part CMP-0007140-4, "CAP, CERM, 0.22 uF, 25 V, +/- 10%, X7R, AEC-Q200 Grade 1, 0603", Cap_Case=0603, Manufacturer=MuRata, Supplier Part Number 1=490-4935-1-ND, TempCo=X7R, Tolerance_%=10%, Value1=Unknown, Value2=25V, ValueDisplayed=0.22uF
C13 C19 C21: library part CMP-0085283-1, "CAP, CERM, 10 µF, 16 V,+/- 10%, X7R, 0805", Cap_Case=0805, Manufacturer="Taiyo Yuden", TempCo=X7R, Tolerance_%=10%, Value2=16V, ValueDisplayed=10µF
C14 C17 C20 C22 C33 C34: library part CMP-0006228-2, "CAP, CERM, 0.1 uF, 16 V, +/- 10%, X7R, 0402", Cap_Case=0402, Manufacturer="Wurth Elektronik", Supplier Part Number 1=732-7532-1-ND, TempCo=X7R, Tolerance_%=10%, Value1=Unknown, Value2=16V, ValueDisplayed=0.1uF
C18: library part CMP-0007867-2, "CAP, CERM, 2.2 uF, 16 V, +/- 10%, X7R, 0805", Cap_Case=0805, Manufacturer=TDK, Supplier Part Number 1=445-1420-1-ND, TempCo=X7R, Tolerance_%=10%, Value1="0.0049 ohm", Value2=16V, ValueDisplayed=2.2uF
C23: library part CMP-0096782-1, "Capacitor Ceramic 2.2uF 35V X7R 10% 1206 T/R", Digikey Part Number=445-173825-1-ND, Manufacturer=TDK, Mouser Part Number=810-C3216X7R1V225KAE, Operating Temperature Range="-55°C to +125°C", TempCo=15%, Temperature Characteristic=X7R, Tolerance_%=10%, ValueDisplayed=2.2uF
C24: library part CMP-0094936-1, "Cap Ceramic 100nF 35V X7R 10% Pad SMD 0402 +125°C Automotive T/R", Manufacturer="TDK Corporation", Operating Temperature Range="-55°C to +125°C", TempCo=15%, Temperature Characteristic=X7R, Tolerance_%=0.1%, ValueDisplayed=100nF
C25: library part CMP-0006370-2, "CAP, CERM, 0.1 uF, 35 V, +/- 10%, X5R, 0402", Cap_Case=0402, Manufacturer="Taiyo Yuden", Supplier Part Number 1=587-1994-1-ND, TempCo=X5R, Tolerance_%=10%, Value1=Unknown, Value2=35V, ValueDisplayed=0.1uF
C26: library part CMP-0007052-4, "CAP, CERM, 1 uF, 35 V, +/- 10%, X7R, 0603", Cap_Case=0603, Manufacturer=TDK, Supplier Part Number 1=445-7414-1-ND, TempCo=X7R, Tolerance_%=10%, Value1=Unknown, Value2=35V, ValueDisplayed=1uF
C27: library part CMP-0006831-4, "CAP, CERM, 1 uF, 16 V, +/- 10%, X7R, 0603", Cap_Case=0603, Manufacturer="Wurth Elektronik", Supplier Part Number 1=710-885012206052, TempCo=X7R, Tolerance_%=10%, Value1=Unknown, Value2=16V, ValueDisplayed=1uF
C30: "No Description Available", Mfr_Name=Kemet
C31: library part CMP-0860569-1, "CAP, CERM, 10 µF, 25 V,+/- 10%, X5R, 0603", Cap_Case=0603, Manufacturer=MuRata, TempCo=X5R, Tolerance_%=10%, Value2=25V, ValueDisplayed=10µF
C32: library part CMP-0007403-4, "CAP, CERM, 0.01 uF, 25 V, +/- 10%, X7R, 0603", Cap_Case=0603, Manufacturer=MuRata, Supplier Part Number 1=490-1520-1-ND, TempCo=X7R, Tolerance_%=10%, Value1=Unknown, Value2=25V, ValueDisplayed=0.01uF
C35 C41: library part CMP-0079154-1, "CAP, CERM, 1 µF, 16 V,+/- 10%, X7R, AEC-Q200 Grade 1, 0603", Cap_Case=0603, Manufacturer=MuRata, Supplier Part Number 1=490-12657-1-ND, TempCo=X7R, Tolerance_%=10%, Value2=16V, ValueDisplayed=1µF
C36: library part CMP-0750153-1, "CAP, CERM, 4.7 µF, 50 V,+/- 10%, X7R, AEC-Q200 Grade 1, 1210", Cap_Case=1210, Manufacturer=MuRata, TempCo=X7R, Tolerance_%=10%, Value2=50V, ValueDisplayed=4.7µF
C37: library part CMP-0006356-2, "CAP, CERM, 0.1 uF, 50 V, +/- 10%, X7R, AEC-Q200 Grade 1, 0402", Cap_Case=0402, Manufacturer=MuRata, Supplier Part Number 1=490-10672-1-ND, TempCo=X7R, Tolerance_%=10%, Value1=Unknown, Value2=50V, ValueDisplayed=0.1uF
C38 C39 C40: library part CMP-0009213-2, "CAP, CERM, 22 uF, 25 V, +/- 10%, X5R, 1210", Cap_Case=1210, Manufacturer=MuRata, Supplier Part Number 1=81-GRM32ER61E226KE15, TempCo=X5R, Tolerance_%=10%, Value1="0.002 ohm", Value2=25V, ValueDisplayed=22uF
D1: library part CMP-0002888-2, "LED, Green, SMD", Color=Green, Manufacturer=Lite-On, Value1=W, Value2=2V
DIAGSW1 MICBIAS1: library part CMP-0055164-1, "Test Point, Miniature, Green, TH", Color=Green, Manufacturer=Keystone, PartNumber=5116, Supplier Part Number 1=36-5116-ND
FID1 FID2 FID3 FID4 FID5 FID6: library part CMP-0077181-1, "Fiducial mark.  There is nothing to buy or mount.", Manufacturer=N/A
H1 H2 H3 H4: library part CMP-0003617-1, "Machine Screw, Round, #4-40 x 1/4, Nylon, Philips panhead", Manufacturer="B&F Fastener Supply", Supplier Part Number 1=H542-ND
H5 H6 H7 H8: library part CMP-0003610-1, "Standoff, Hex, 0.5\"L #4-40 Nylon", Manufacturer=Keystone, Supplier Part Number 1=36-1902C-ND
H9 H10 H11 H12: library part CMP-0003620-1, "Bumpon, Hemisphere, 0.44 X 0.20, Clear", Manufacturer=3M, Supplier Part Number 1=SJ5303-7-ND
J1 J3: library part CMP-0055479-2, "Terminal Block, 100mil, 2x1, 6A, 63V, TH", Manufacturer="Phoenix Contact", Supplier Part Number 1=71C4107
J2: library part CMP-0087503-1, "TERM BLK 2POS SIDE ENTRY 5MM PCB", Current_A=16A, Manufacturer="Würth Elektronik", Voltage_V=300V
J4: library part CMP-0075410-2, "Header, 100mil, 5x2, Gold, TH", Color=Black, Current_A=6.3A, Manufacturer=Samtec, Supplier Part Number 1=SAM1028-05-ND, Voltage_V=550V
J5: library part CMP-0074987-1, "Audio Jack, 3.5mm, Stereo, R/A, SMT", Manufacturer=Switchcraft, Supplier Part Number 1=SC1488-1-ND
J6 J10: library part CMP-0002334-1, "Header, 100mil, 3x1, Gold, TH", Manufacturer="Sullins Connector Solutions", Supplier Part Number 1=S1011E-03-ND
J7: library part CMP-0054598-1, "Header, 2.54mm, 2x2, Gold, TH", Color=Black, Current_A=3A, Manufacturer="Sullins Connector Solutions", PartNumber=PBC02DAAN, Supplier Part Number 1=S2011E-02-ND, Voltage_V=1.8kV
J8: library part CMP-0075407-2, "Header, 100mil, 3x1, Gold, TH", Color=Black, Current_A=6.3A, Manufacturer=Samtec, Supplier Part Number 1=SAM1029-03-ND, Voltage_V=550V
J9: library part CMP-0055951-1, "Connector, Header, High Speed, 20 pairs, SMT", Manufacturer=Samtec, Supplier Part Number 1=SAM8128-ND
J12: library part CMP-0075408-3, "Header, 100mil, 4x2, Gold, TH", Color=Black, Current_A=6.3A, Manufacturer=Samtec, Supplier Part Number 1=SAM1028-04-ND, Voltage_V=550V
K1: library part CMP-0082600-1, "Relay, SPST-NO (1 Form A), 4 A, SMD", Contact Rating_A=4A, Manufacturer="Omron Electronic Components", Supplier Part Number 1=Z6607CT-ND
L1: "Inductor Power Shielded Wirewound 10uH 20% 100KHz Ferrite 3.4A 0.0611Ohm DCR Automotive T/R", Package="NON STANDARD-2 TDK"
L2: "Inductor Power Shielded Wirewound 10uH 20% 100KHz Ferrite 3.4A 0.0611Ohm DCR Automotive T/R", Manufacturer="TDK Corporation", Package="NON STANDARD-2 TDK"
L3: library part CMP-0003285-2, "Ferrite Bead, 600 ohm @ 100 MHz, 1 A, 0603", Manufacturer="Wurth Elektronik", Supplier Part Number 1=732-6703-1-ND, Value1="0.2 ohm", Value2=1A, ValueDisplayed="600 ohm"
L4: library part CMP-0083752-1, "Inductor, Shielded, Metal Composite, 2.2 µH, 2.2 A, 0.1 ohm, SMD", Manufacturer=Littelfuse, Value1="0.1 ohm", Value2=2.2A, ValueDisplayed=2.2µH
L5: library part CMP-0121228-1, "Shielded Wirewound Inductor 3.9uH 30% 4200mA 0.0264Ω SMD", Manufacturer=Murata, Operating Temperature Range="-40°C to +85°C", Part Number=1255AY-3R9N{}P3, Test Frequency=100kHz, Tolerance_%=0.3%
Logo1: library part CMP-0074838-1, "Texas Instrument Corporate Signature"
Logo2: library part CMP-0074844-1
Logo3: library part CMP-0074847-1, "FCC_disclaimer"
Logo4: library part CMP-0074769-3, Manufacturer="Texas Instruments"
MIC1M MIC1P MIC2M MIC2P: library part CMP-0055140-2, "Test Point, Miniature, Orange, TH", Color=Orange, Manufacturer="Keystone Electronics", Supplier Part Number 1=36-5003-ND
MK1 MK2: library part CMP-0001912-2, "Microphone, Condenser, Analog, Omnidirectional, -42DB, TH", Manufacturer="PUI Audio", Supplier Part Number 1=668-1149-ND
R1 R4: library part CMP-0021974-2, "RES, 5.60, 1%, 0.33 W, 0805", Manufacturer="Susumu Co Ltd", Power_W=330mW, Supplier Part Number 1=RL12S5.6FCT-ND, TempCo="200 ppm/C", Tolerance_%=1%, Value2=0.33W, Value_Code=5R60, ValueDisplayed=5.60
R2 R3 R5: library part CMP-0023346-3, "RES, 100 k, 0.1%, 0.063 W, 0603", Manufacturer="TE Connectivity", Power_W=63mW, Supplier Part Number 1=279-CPF0603B100KE, TempCo="25 ppm/C", Tolerance_%=0.1%, Value2=0.063W, Value_Code=100k
R6 R7 R15 R16: library part CMP-0025885-5, "RES, 0, 5%, 0.1 W, 0603", Manufacturer=Yageo, Power_W=100mW, Supplier Part Number 1=311-0.0GRCT-ND, TempCo="200 ppm/C", Tolerance_%=5%, Value2=0.1W, Value_Code=0000, ValueDisplayed=0
R8 R9 R10 R11: library part CMP-0086358-1, "RES, 0, 0%, 0.25 W, AEC-Q200 Grade 0, 0603", Manufacturer=Rohm, Power_W=250mW, Tolerance_%=0%, Value2=0.25W, Value_Code=0000, ValueDisplayed=0
R12 R13 R14 R17: library part CMP-0025730-4, "RES, 1.1 k, 5%, 0.1 W, AEC-Q200 Grade 0, 0603", Manufacturer=Vishay-Dale, Power_W=100mW, Supplier Part Number 1=541-1.1KGCT-ND, TempCo="200 ppm/C", Tolerance_%=5%, Value2=0.1W, Value_Code=1k10, ValueDisplayed=1.1k
R18 R19: library part CMP-0022883-5, "RES, 1.50 k, 1%, 0.1 W, 0603", Manufacturer=Yageo, Power_W=100mW, Supplier Part Number 1=311-1.50KHRCT-ND, TempCo="100 ppm/C", Tolerance_%=1%, Value2=0.1W, Value_Code=1k50, ValueDisplayed=1.50k
R20: library part CMP-0016598-3, "RES, 11.8 k, 1%, 0.25 W, AEC-Q200 Grade 0, 1206", Manufacturer=Vishay-Dale, Power_W=250mW, Supplier Part Number 1=541-11.8KFCT-ND, TempCo="100 ppm/C", Tolerance_%=1%, Value2=0.25W, Value_Code=11k8, ValueDisplayed=11.8k
R21: library part CMP-0022425-5, "RES, 442, 1%, 0.1 W, AEC-Q200 Grade 0, 0603", Manufacturer=Vishay-Dale, Power_W=100mW, Supplier Part Number 1=541-442HCT-ND, TempCo="100 ppm/C", Tolerance_%=1%, Value2=0.1W, Value_Code=442R, ValueDisplayed=442
R22: library part CMP-0016952-3, "RES, 3.74 k, 1%, 0.25 W, AEC-Q200 Grade 0, 1206", Manufacturer=Vishay-Dale, Power_W=250mW, Supplier Part Number 1=541-3.74KFCT-ND, TempCo="100 ppm/C", Tolerance_%=1%, Value2=0.25W, Value_Code=3k74, ValueDisplayed=3.74k
R23 R24: library part CMP-0026756-1, "RES, 1.50 k, 1%, 0.063 W, AEC-Q200 Grade 0, 0402", Manufacturer="Stackpole Electronics Inc", Power_W=63mW, Supplier Part Number 1=RMCF0402FT1K50CT-ND, TempCo="100 ppm/C", Tolerance_%=1%, Value2=0.063W, Value_Code=1k50, ValueDisplayed=1.50k
R26: library part CMP-0026906-3, "RES, 330, 5%, 0.063 W, AEC-Q200 Grade 0, 0402", Manufacturer=Vishay-Dale, Power_W=63mW, Supplier Part Number 1=541-330JCT-ND, TempCo="200 ppm/C", Tolerance_%=5%, Value2=0.063W, Value_Code=330R, ValueDisplayed=330
SW1: library part CMP-0002143-3, "Switch, Tactile, SPST-NO, 0.05A, 12V, SMT", CurrentRating_mA=50A, Manufacturer=E-Switch, PartNumber=TL1015AF160QG, Supplier Part Number 1=EG4344CT-ND
SW2: library part CMP-0082634-2, "Switch, DPDT, 0.15 A, 30 VDC, TH", CurrentRating_mA=150A, Manufacturer=Grayhill, Supplier Part Number 1=GH7722-ND
U1: library part CMP-0088358-2, "22-W Mono Automotive Digital-audio Amplifier with Load Dump and I2C Diagnostics", Manufacturer="Texas Instruments", Max Supply Voltage=18V, Min Supply Voltage=4.5V, Nominal Supply Current=16mA, Operating Temperature Range=to, Output Current Per Channel=3.5A, Power At Speaker R="22W @ 4Ω", Voltage Gain=20dB
U2: library part CMP-0121019-1, "Automotive Low Power Stereo Audio Codec with integrated programmable boost, micbias and diagnostics", Manufacturer="Texas Instruments", Max Supply Voltage=3.6V, Min Supply Voltage=1.08V, Operating Temperature Range="-40°C to +150°C"
U3: library part CMP-0077252-2, "Automotive-Grade 2-A, High-Accuracy, Low-Noise, LDO Voltage Regulator, RGR0020A (VQFN-20)", Alternate Manufacturer="Texas Instruments"
U4: "No Description Available", Mfr_Name="Texas Instruments"
U5: library part CMP-0095155-1, "36-V, 1-A/2-A Buck Converter with <3 µA IQ at 150°C TJMAX in 4-mm2 HotRod™ QFN", Manufacturer="Texas Instruments", Max Supply Voltage=36V, Min Supply Voltage=3V, Nominal Supply Current=1.2uA, Operating Temperature Range="-40°C to +150°C", Output Voltage=5/1-34.2V, Switching Frequency=200-2200kHz
ZZ1: library part CMP-0003616-3
ZZ2: library part CMP-0077236-1
ZZ3: library part CMP-0077237-1
ZZ4: library part CMP-0077238-1

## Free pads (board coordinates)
  round 275.59 hole 129.92 unplated mask+5: 1(180,750) 1(180,1950)

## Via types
v1: diameter 20, hole 10, Top Layer to Bottom Layer, tented both sides, 127 vias
v2: diameter 19.68, hole 7.87, Top Layer to Bottom Layer, 19 vias
v3: diameter 19.68, hole 7.87, Top Layer to Bottom Layer, tented both sides, 5 vias

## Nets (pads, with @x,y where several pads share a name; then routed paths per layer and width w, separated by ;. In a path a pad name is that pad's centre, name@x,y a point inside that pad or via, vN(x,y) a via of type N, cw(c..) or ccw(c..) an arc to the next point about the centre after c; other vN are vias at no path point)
+3.3V: AVDD.1 C13.1 C14.1 C19.1 C20.1 IOVDD.1 J8.2 L3.2 R2.1 R3.1 R18.1 R19.1 SW1.1 U2.6 U2.23 | length 3014.8
  Top Layer w10: v1(850.5,943.5) L3.2@885,943.5 ; R19.1@950,1262.01 v1(984.5,1262.01) ; R18.1@950,1487.99 v1(984.5,1487.99) ; v1(1279.68,2609.07) SW1.1@1279.68,2643.58 ; v1(1319.05,2609.07) SW1.1@1319.05,2643.58 ; v1(1646.48,1149.06) 1678.42,1149.06 R3.1@1688.5,1138.98 ; R2.1@2408.77,1393.68 v1(2408.77,1428.18)
  PWR w10: IOVDD.1@410,2005.5 526.21,1889.29 526.21,1583.56 687.44,1422.33 687.44,1249.97 768.01,1169.4 v1(1180.25,1169.4)
  Signal w10: v1(1362.24,1099.54) 1547.03,1099.54 2013.34,1565.85 2189.53,1565.85 2360.9,1737.22 AVDD.1@2360.9,1839.35
  other v1: 1530.27,1129.5 1152.09,1369.51 1180.91,1369.51
"+3.3V EXT": C30.2 C31.1 D1.1 J8.1 R20.2 U3.1 U3.19 U3.20
"+3.3V MB": C34.2 J8.3 R23.2 R24.2 U4.7 | length 148.7
  Top Layer w10: R24.2@410,1276.38 v1(441.38,1276.38) ; R23.2@410,1483.62 v1(441.38,1483.62) ; U4.7@567.25,1392.8 613.11,1392.8 620,1399.69 C34.2@620,1403.62 v1(646.38,1403.62)
+5.0V: C38.1 C39.1 C40.1 L5.2 U3.14 U3.15 U3.16 U3.17 U5.8
BCLK1: BCLK1.1 J4.3 J9.37 R8.2 | length 2472.5
  Top Layer w10: v1(131.14,1082.28) 185.68,1136.82 278.35,1136.82 298.86,1157.32 298.86,1200.12 245,1253.97 245,1555 277.44,1587.44 277.44,1697.46 381.05,1801.08 579.17,1801.08 BCLK1.1@630.25,1750 780.25,1600 1085,1600 J4.3@1135,1650 1185,1700 1459.67,1700 1485,1674.67 1485,1607 1384.5,1506.5 R8.2@1330,1506.5
  Bottom Layer w10: J9.37@83.35,1082.28 v1(131.14,1082.28)
DIN1: DIN1.1 J4.5 J9.32 R9.2 | length 2343
  Top Layer w10: v1@278.86,1174.07 v1(278.86,1176.77) 243.62,1212.01 94.94,1212.01 77.55,1229.39 77.55,1589.85 355.32,1867.62 822.12,1867.62 DIN1.1@960,2005.5 ; R9.2@1135,1506.5 1135,1550 J4.5@1235,1650
  Bottom Layer w10: v1(278.86,1176.77) J9.32@326.65,1176.77 ; DIN1.1@960,2005.5 1183.66,1781.84 1183.66,1701.34 J4.5@1235,1650
DIN2: J9.34
DOUT1: DOUT1.1 J4.7 J9.27 R10.2 | length 2303.5
  Top Layer w10: v1(131.14,1239.76) 109.56,1261.35 109.56,1591.87 365.28,1847.59 1051.8,1847.59 DOUT1.1@1209.85,2005.65 ; R10.2@1200,1506.5 1200,1542.8 1248.61,1591.41 1276.41,1591.41 J4.7@1335,1650
  Bottom Layer w10: J9.27@83.35,1239.76 v1(131.14,1239.76) ; DOUT1.1@1210,2005.5 1281.84,1933.66 1281.84,1703.16 J4.7@1335,1650
FSYNC1: FSYNC1.1 J4.9 J9.39 R11.2 | length 3567.6
  Top Layer w10: v1(131.14,1050.79) 48.74,1133.19 48.74,1592.66 348.08,1891.99 693.33,1891.99 889.13,2087.8 1733.7,2087.8 1860.9,1960.6 FSYNC1.1@1860.9,1839.35 ; R11.2@1265,1506.5 1265,1538.66 1315.77,1589.43 1374.43,1589.43 J4.9@1435,1650
  Bottom Layer w10: J9.39@83.35,1050.79 v1(131.14,1050.79) ; J4.9@1435,1650 1671.55,1650 FSYNC1.1@1860.9,1839.35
